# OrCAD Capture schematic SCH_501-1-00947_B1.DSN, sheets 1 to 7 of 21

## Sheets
1 P05_POWER DC-DC: size A2
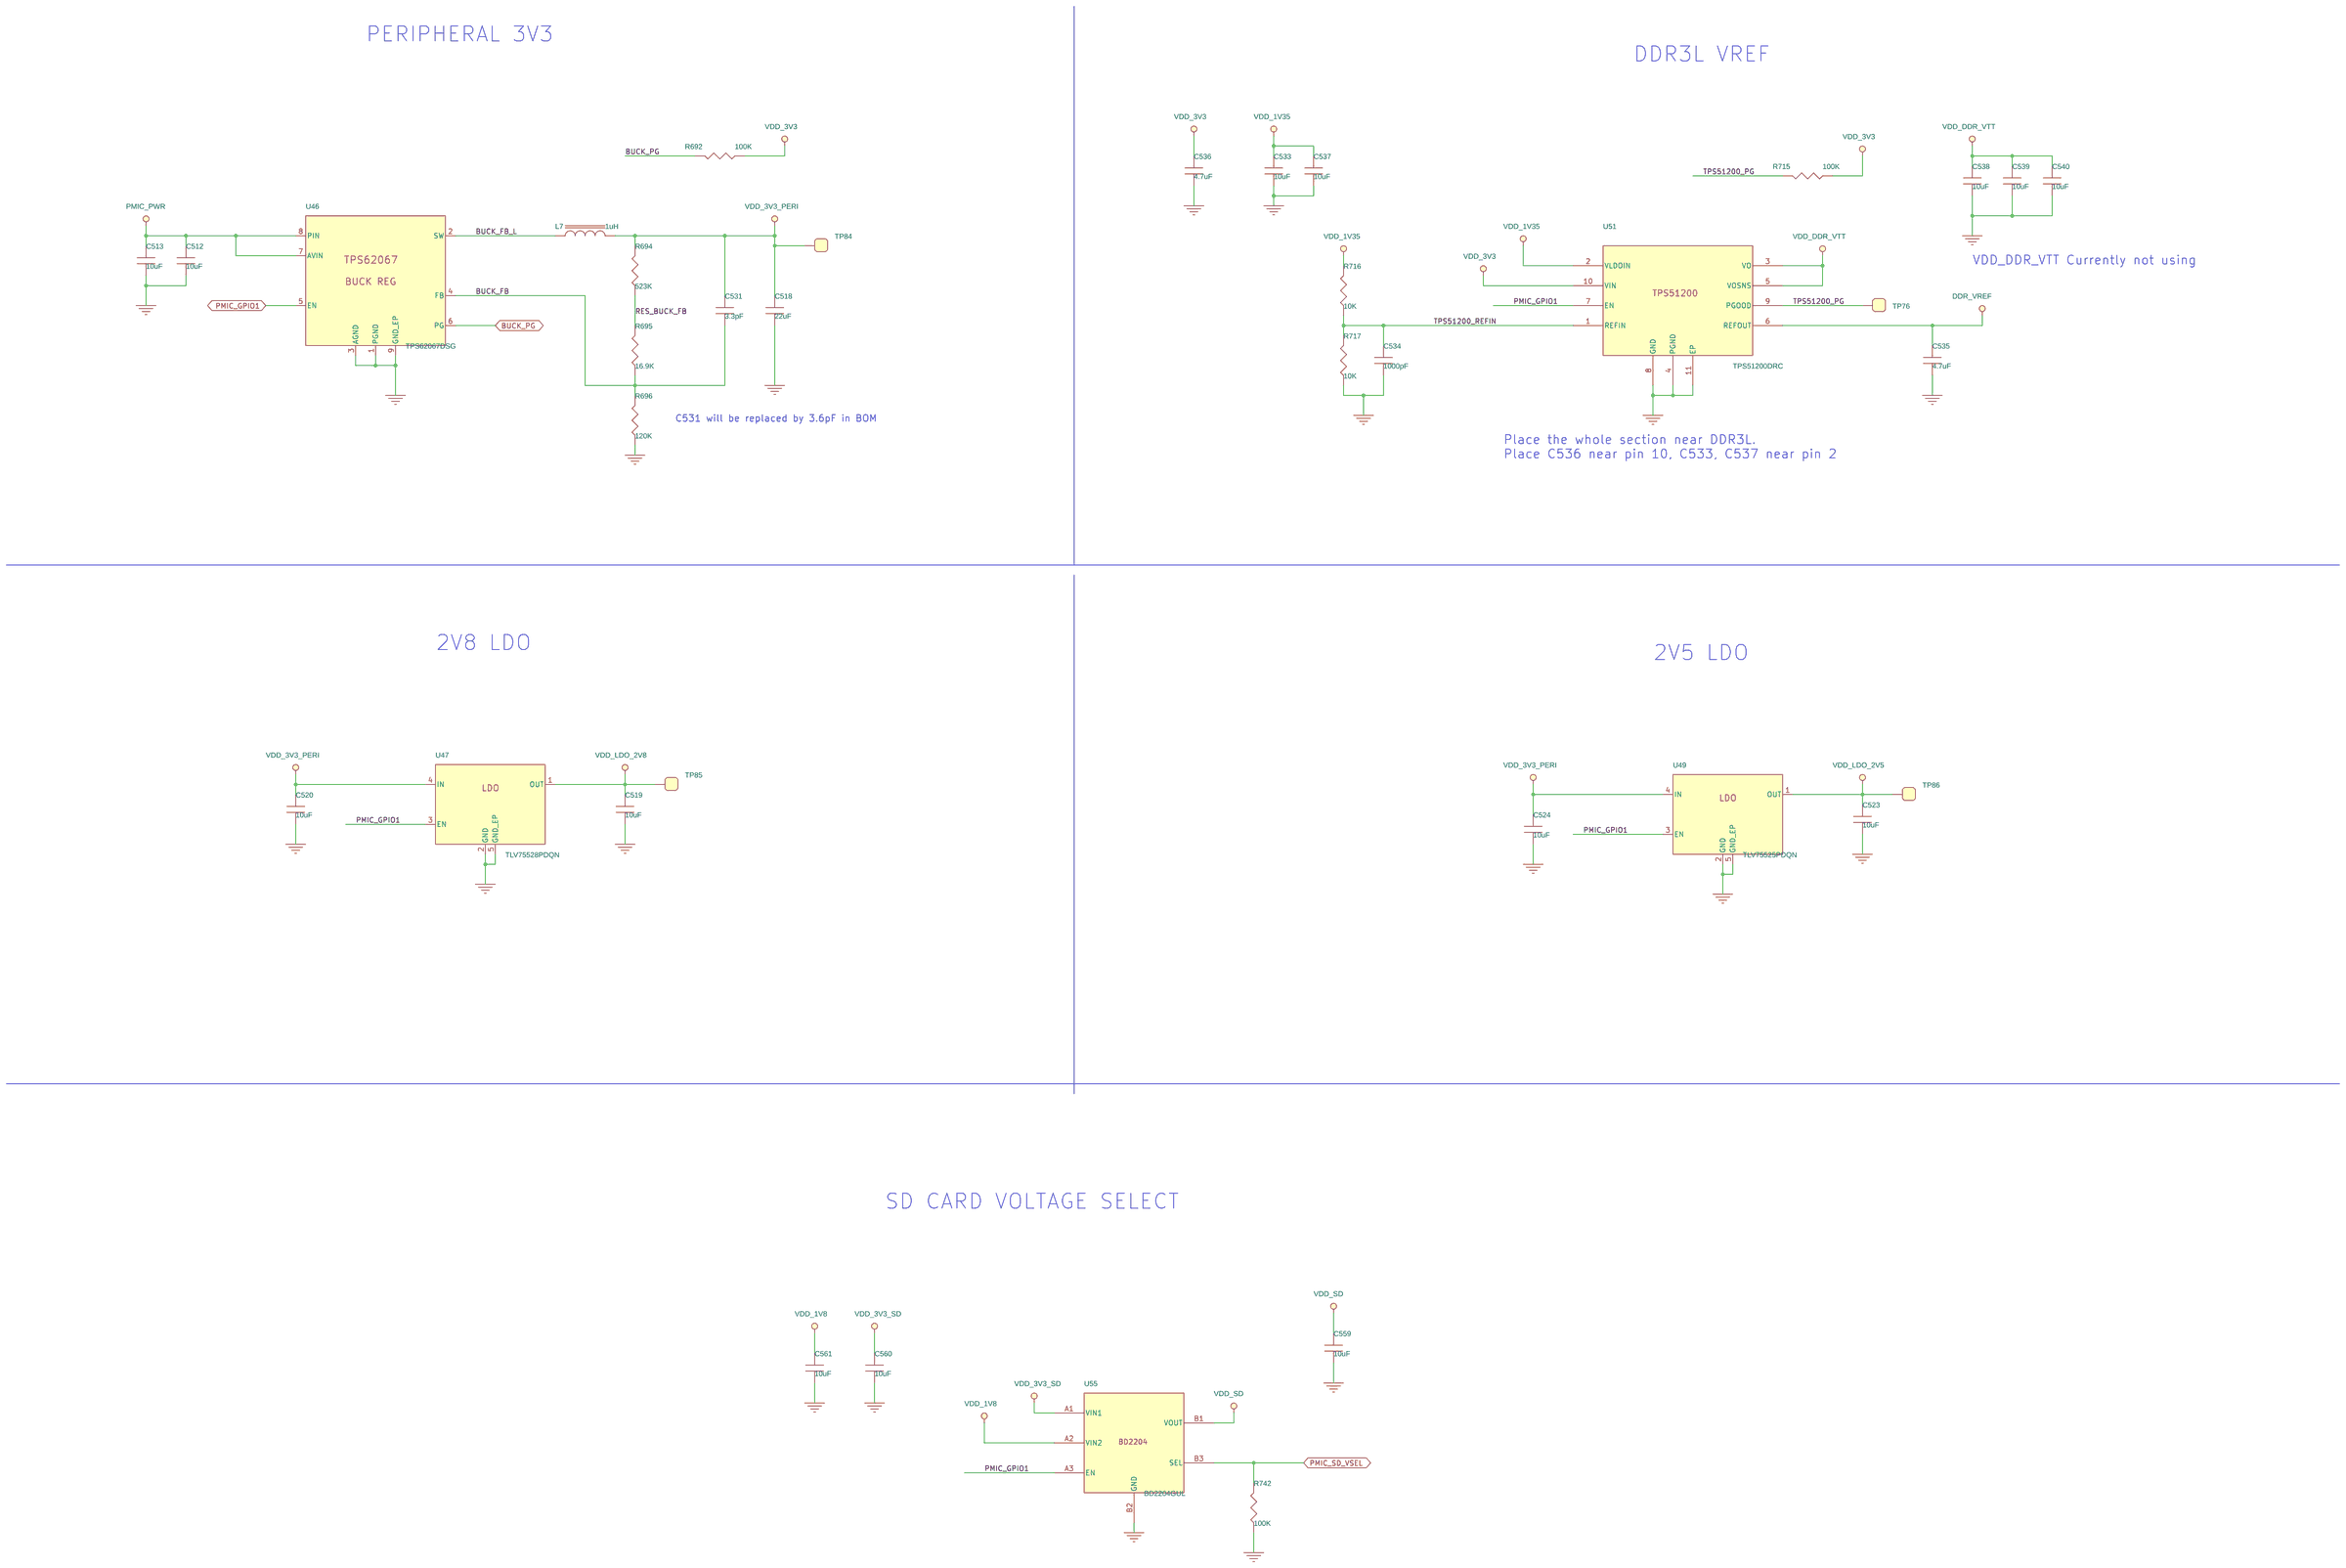
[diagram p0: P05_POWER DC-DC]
2 P01_COVER_PAGE
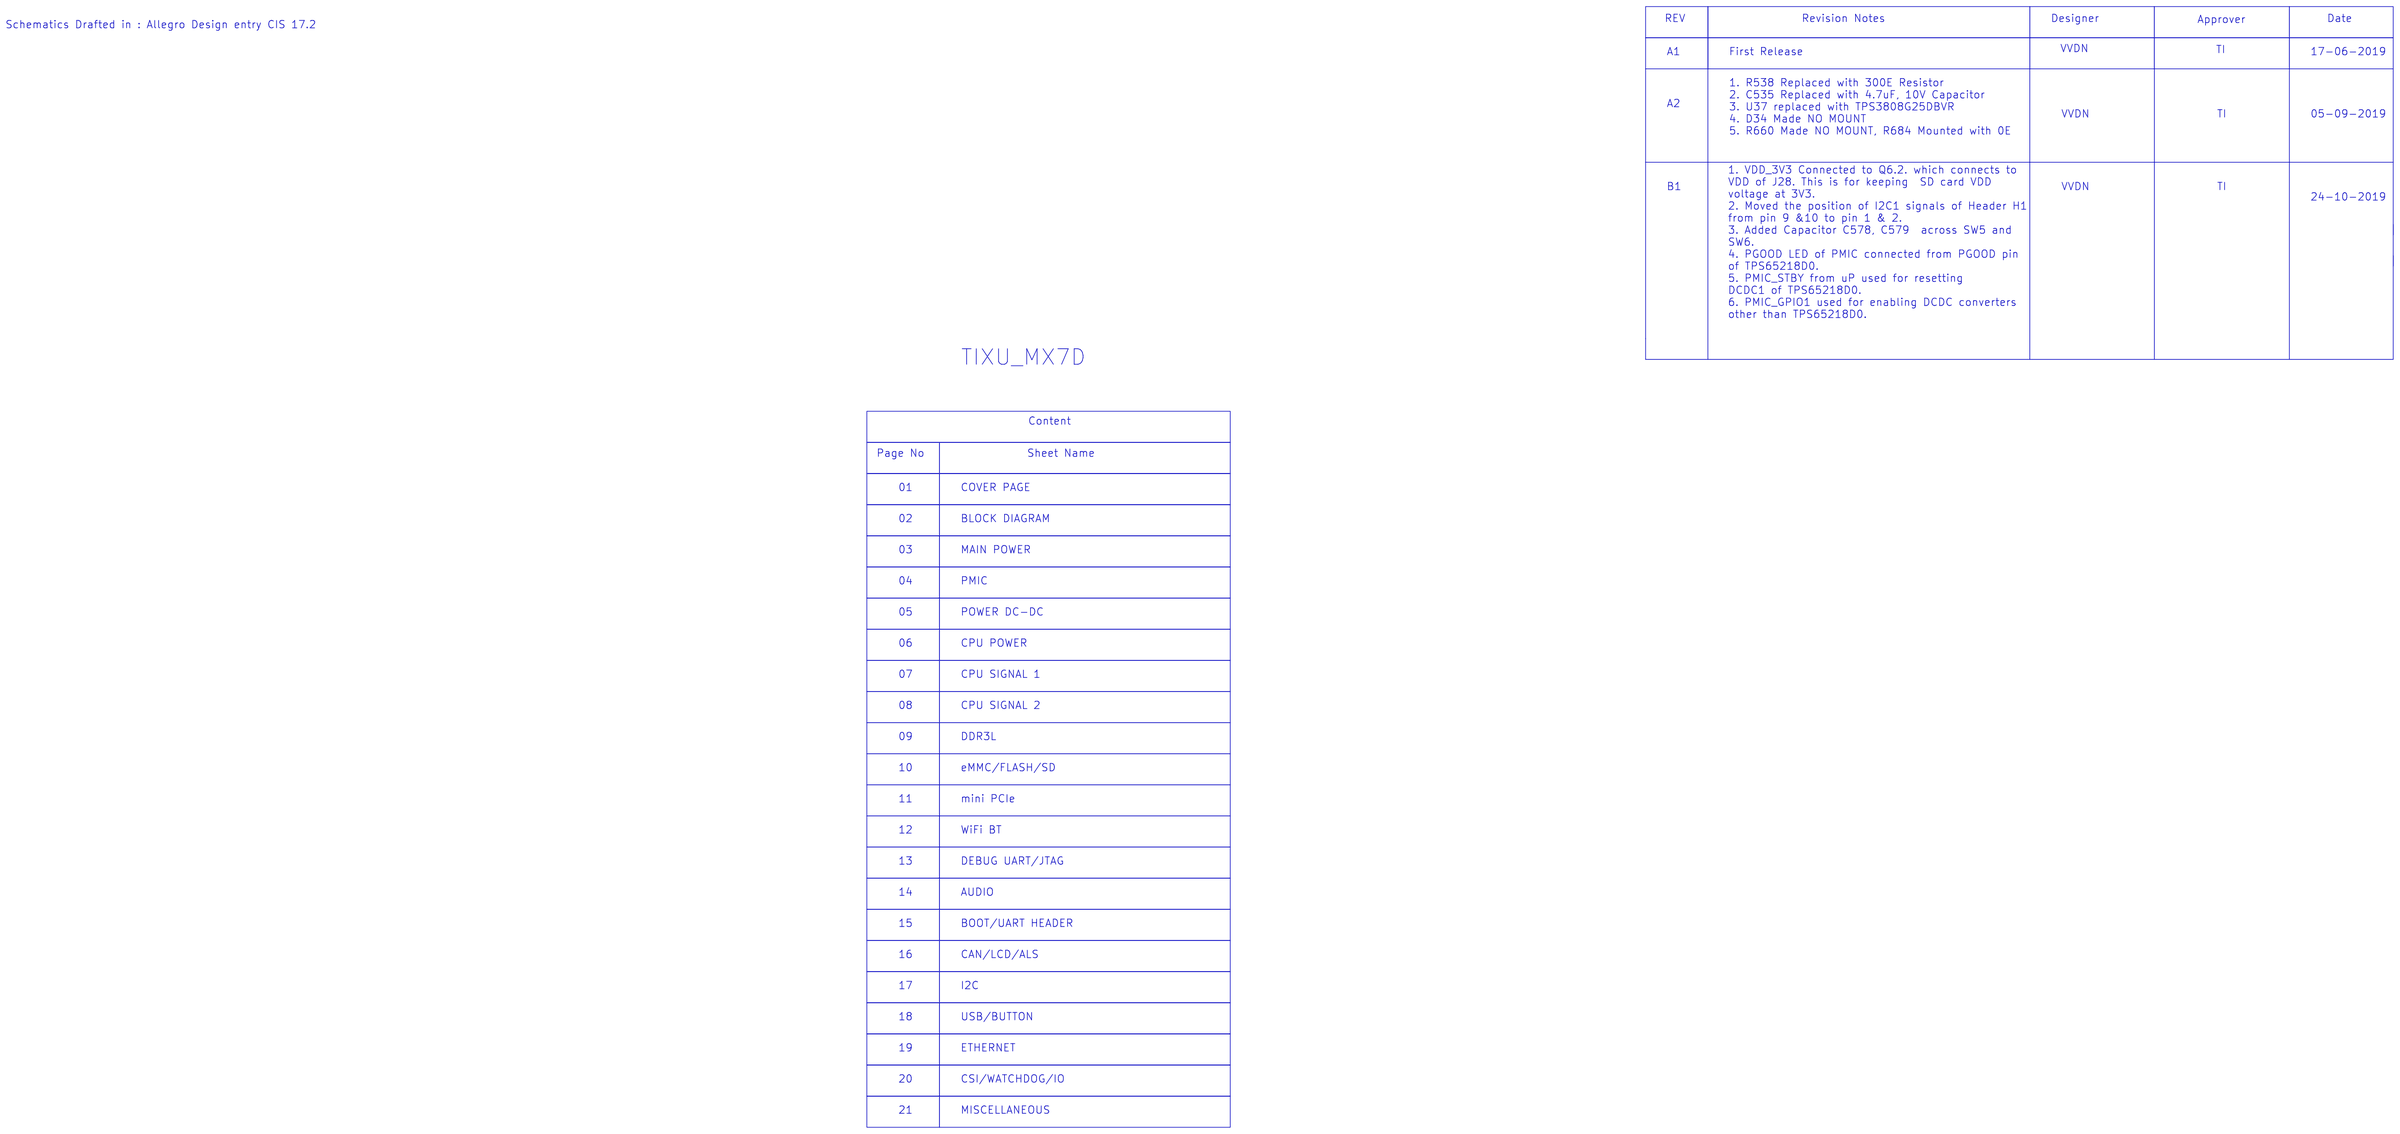
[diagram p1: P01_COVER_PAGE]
3 P02_BLOCK_DIAGRAM
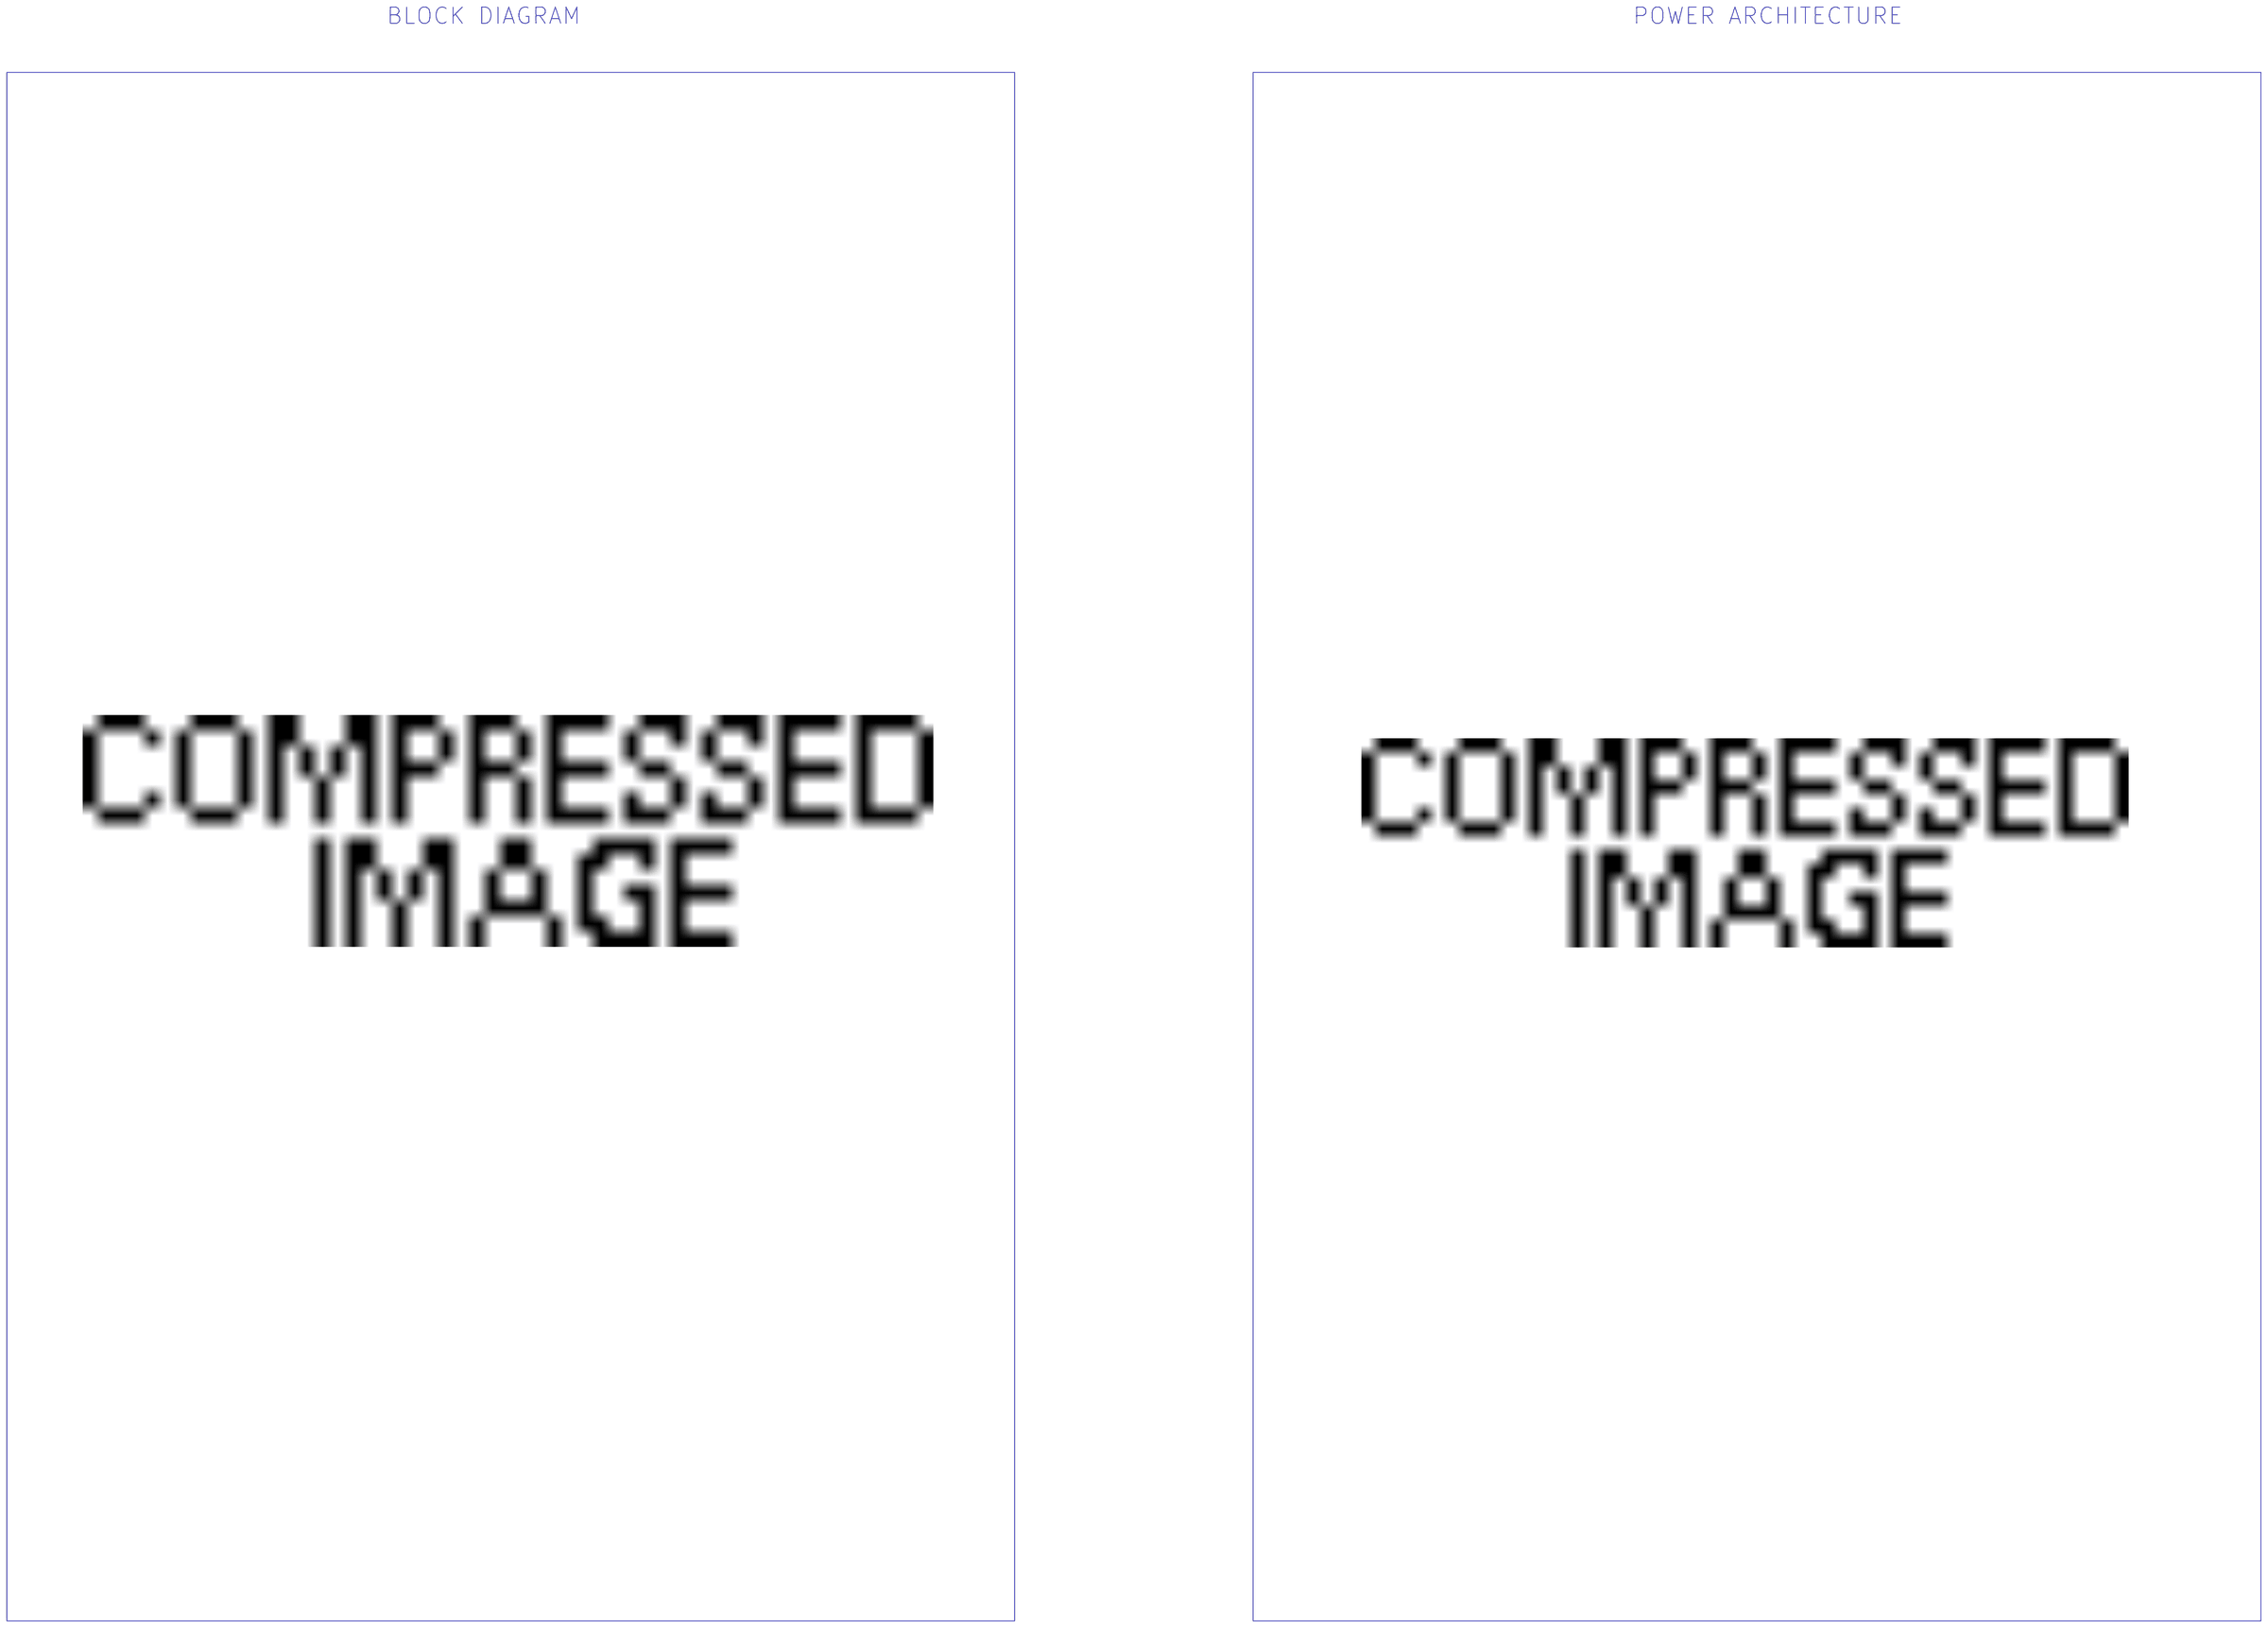
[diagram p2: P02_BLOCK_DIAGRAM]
4 P03_MAIN POWER: size A2
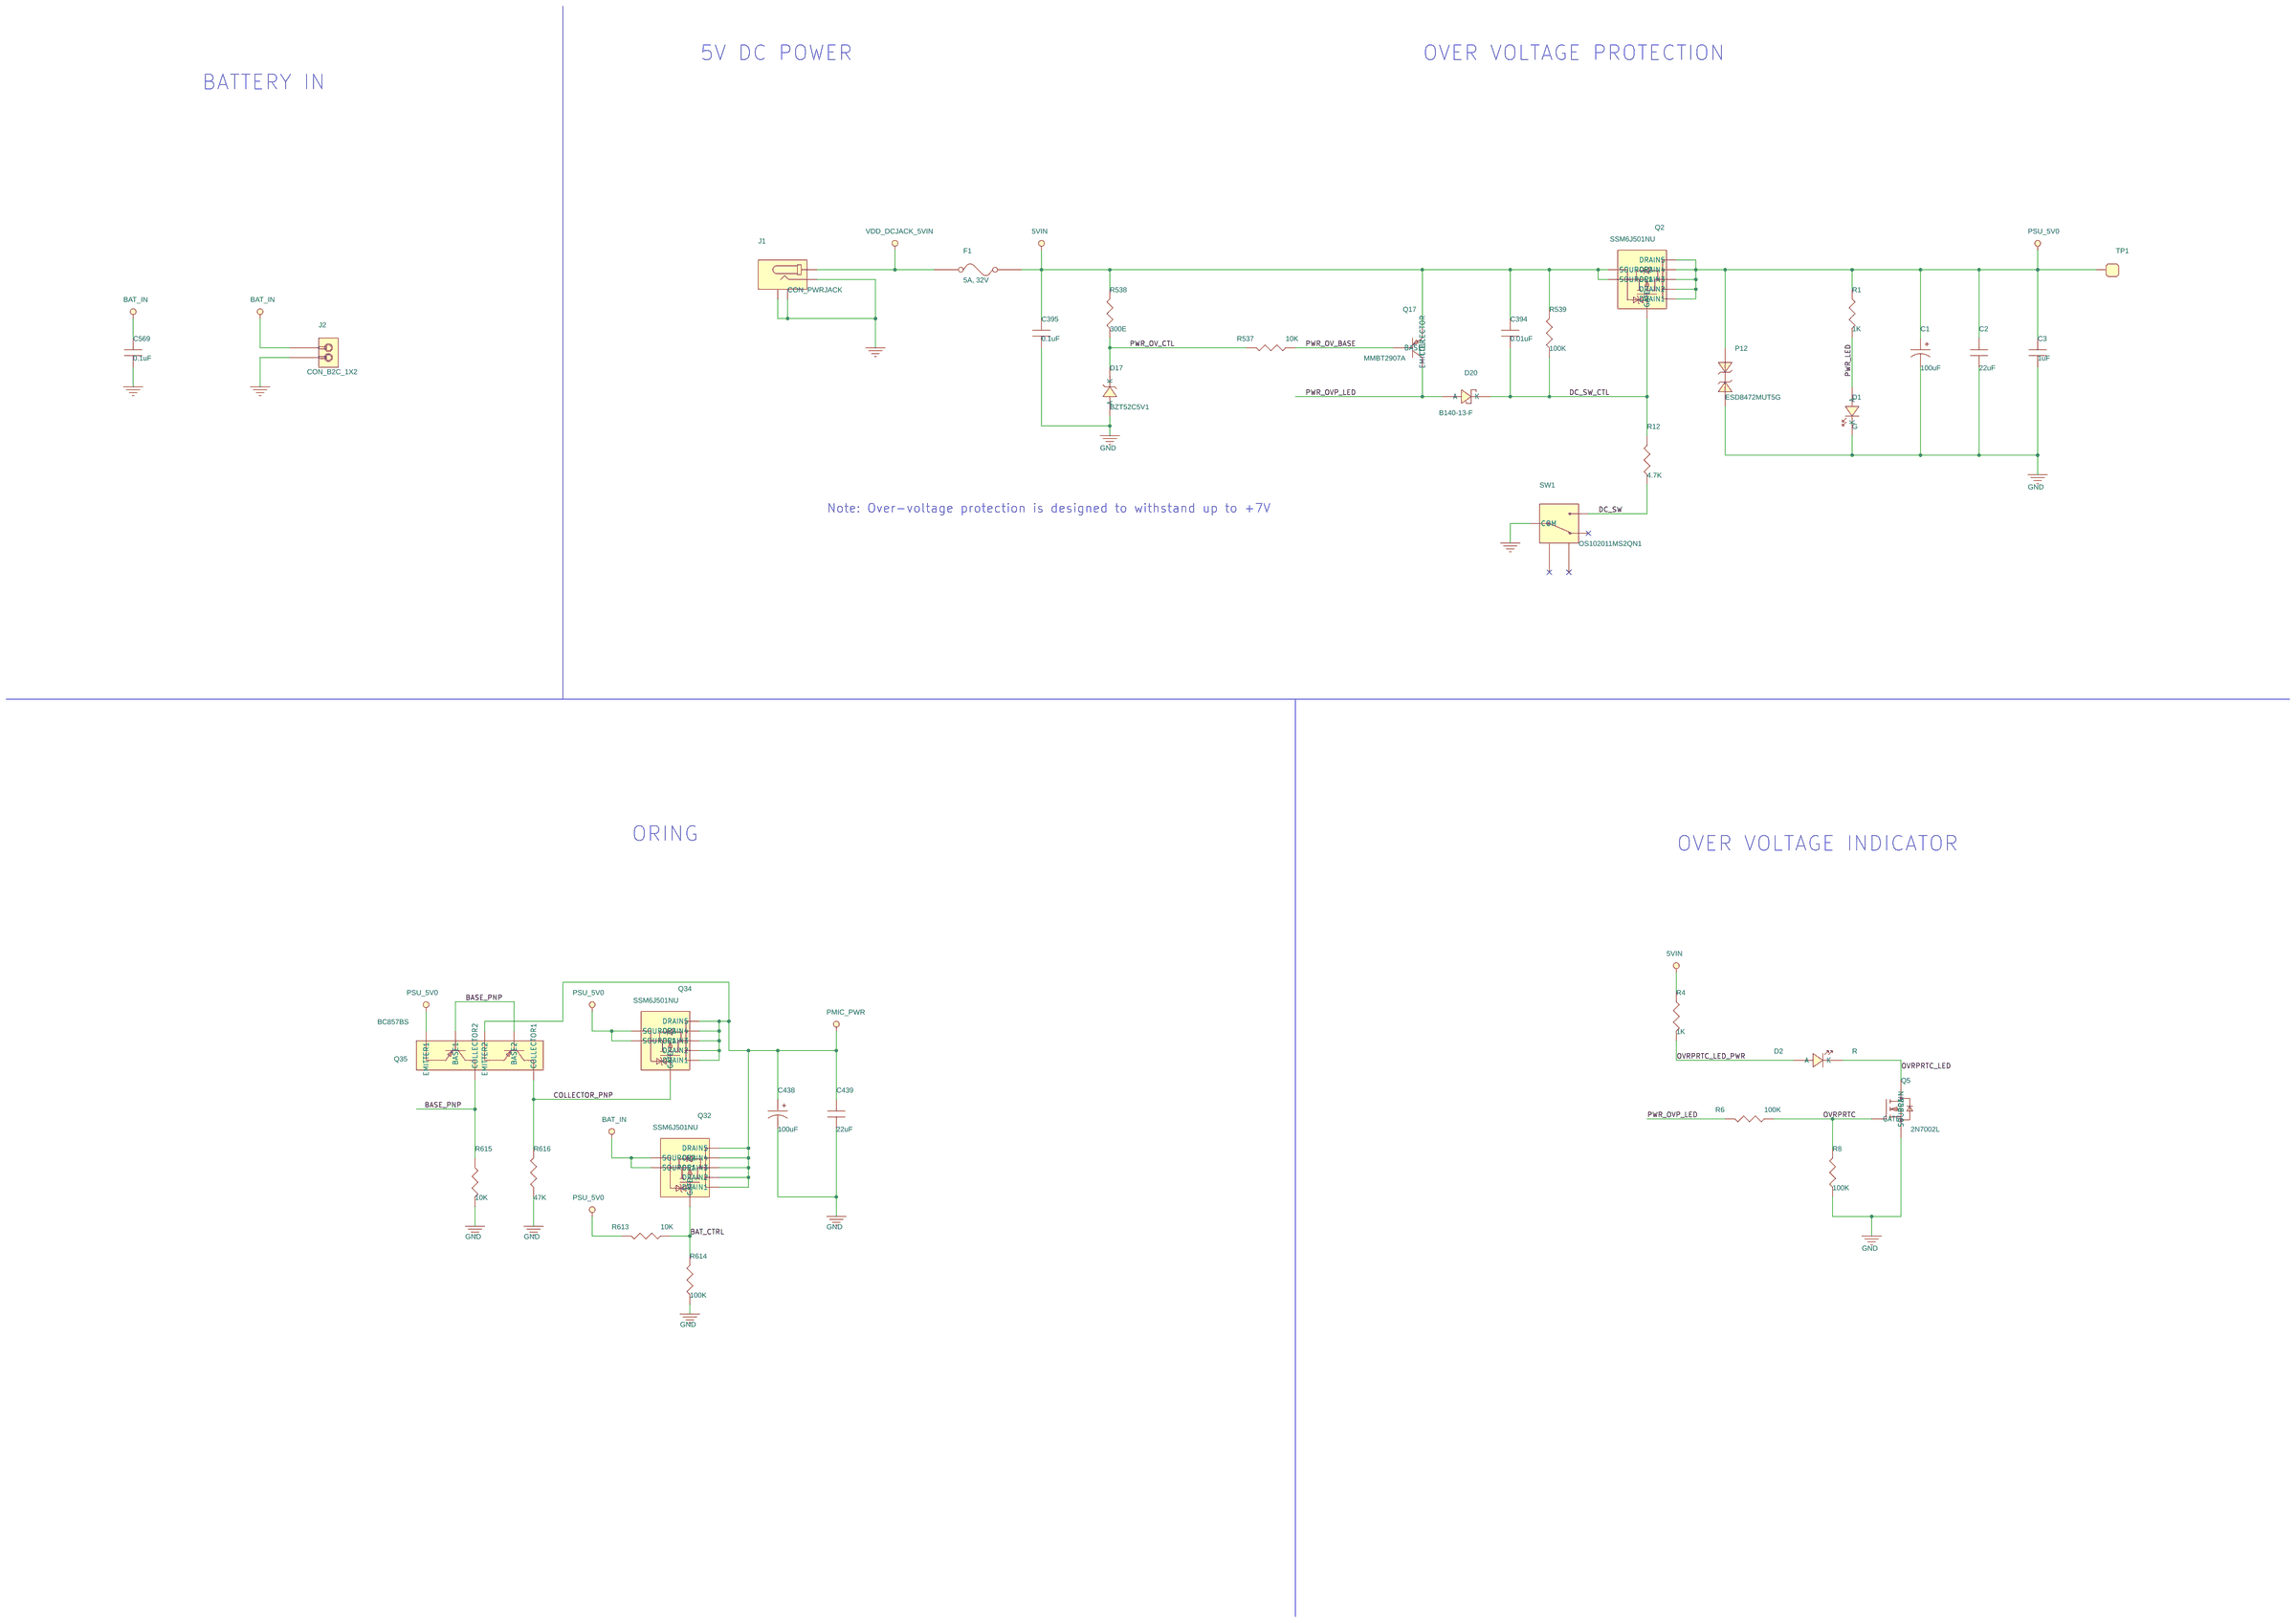
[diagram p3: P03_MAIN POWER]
5 P04_PMIC: size A2
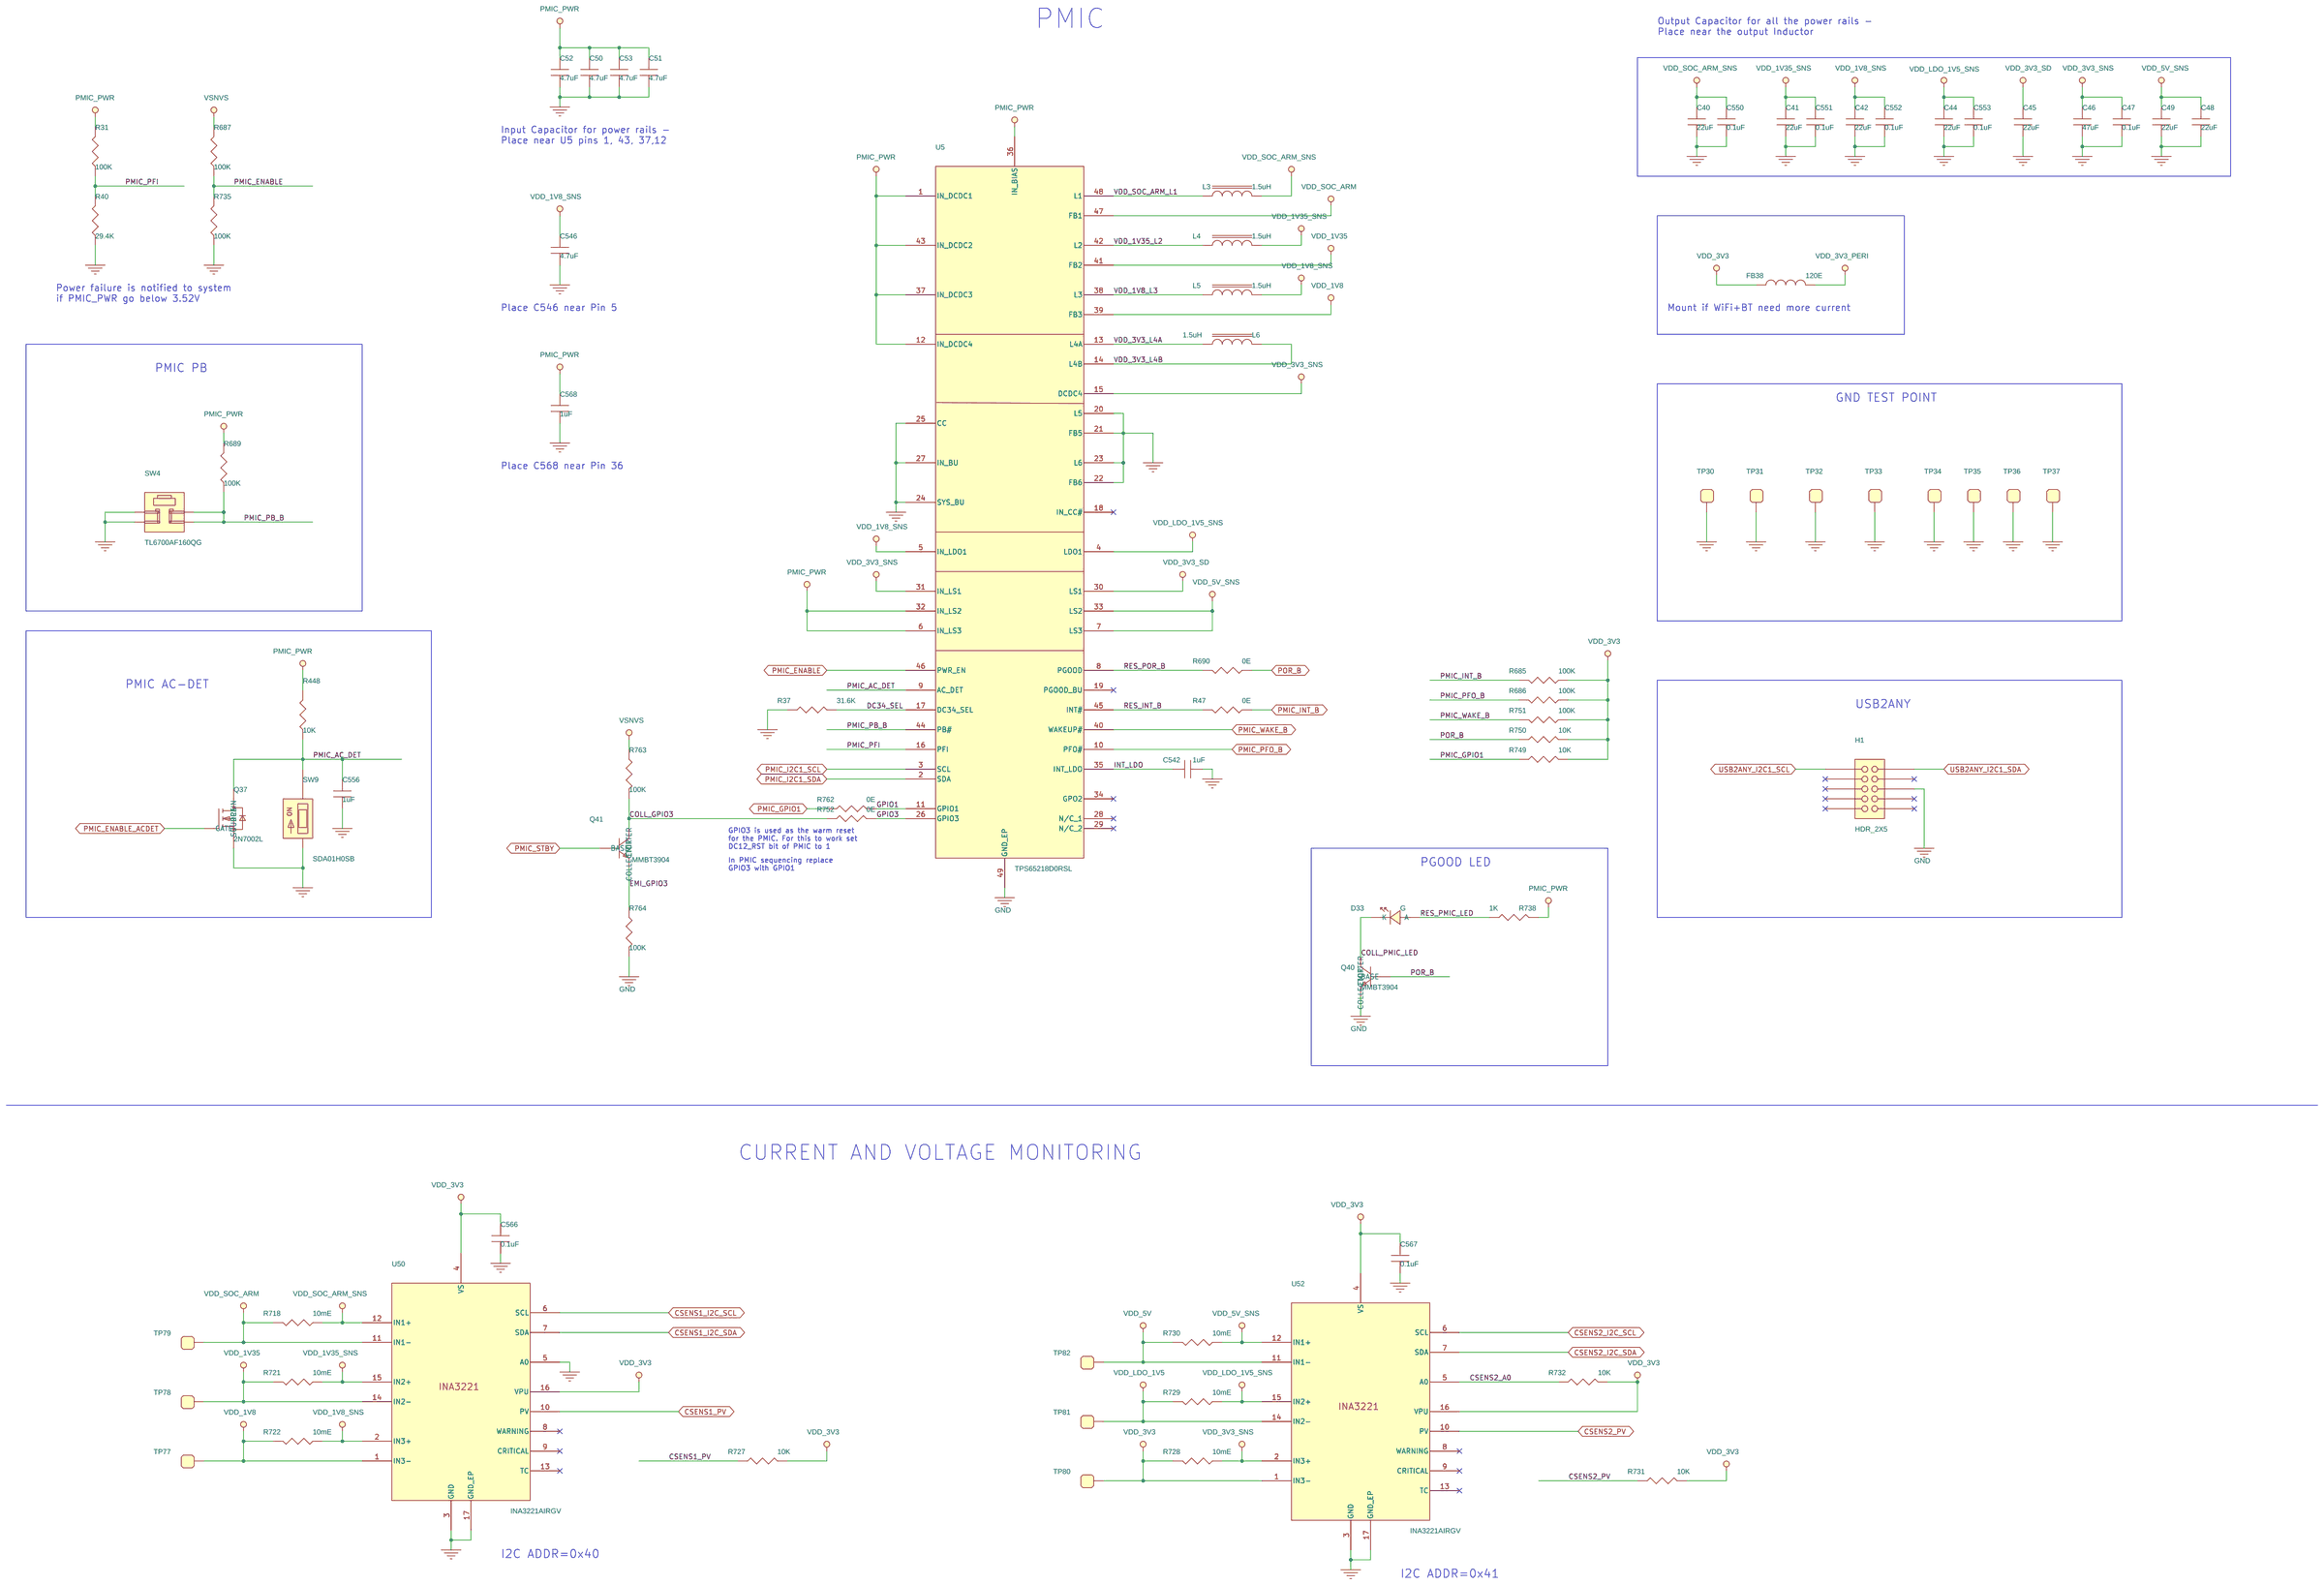
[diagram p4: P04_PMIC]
6 P06_CPU POWER: size A2
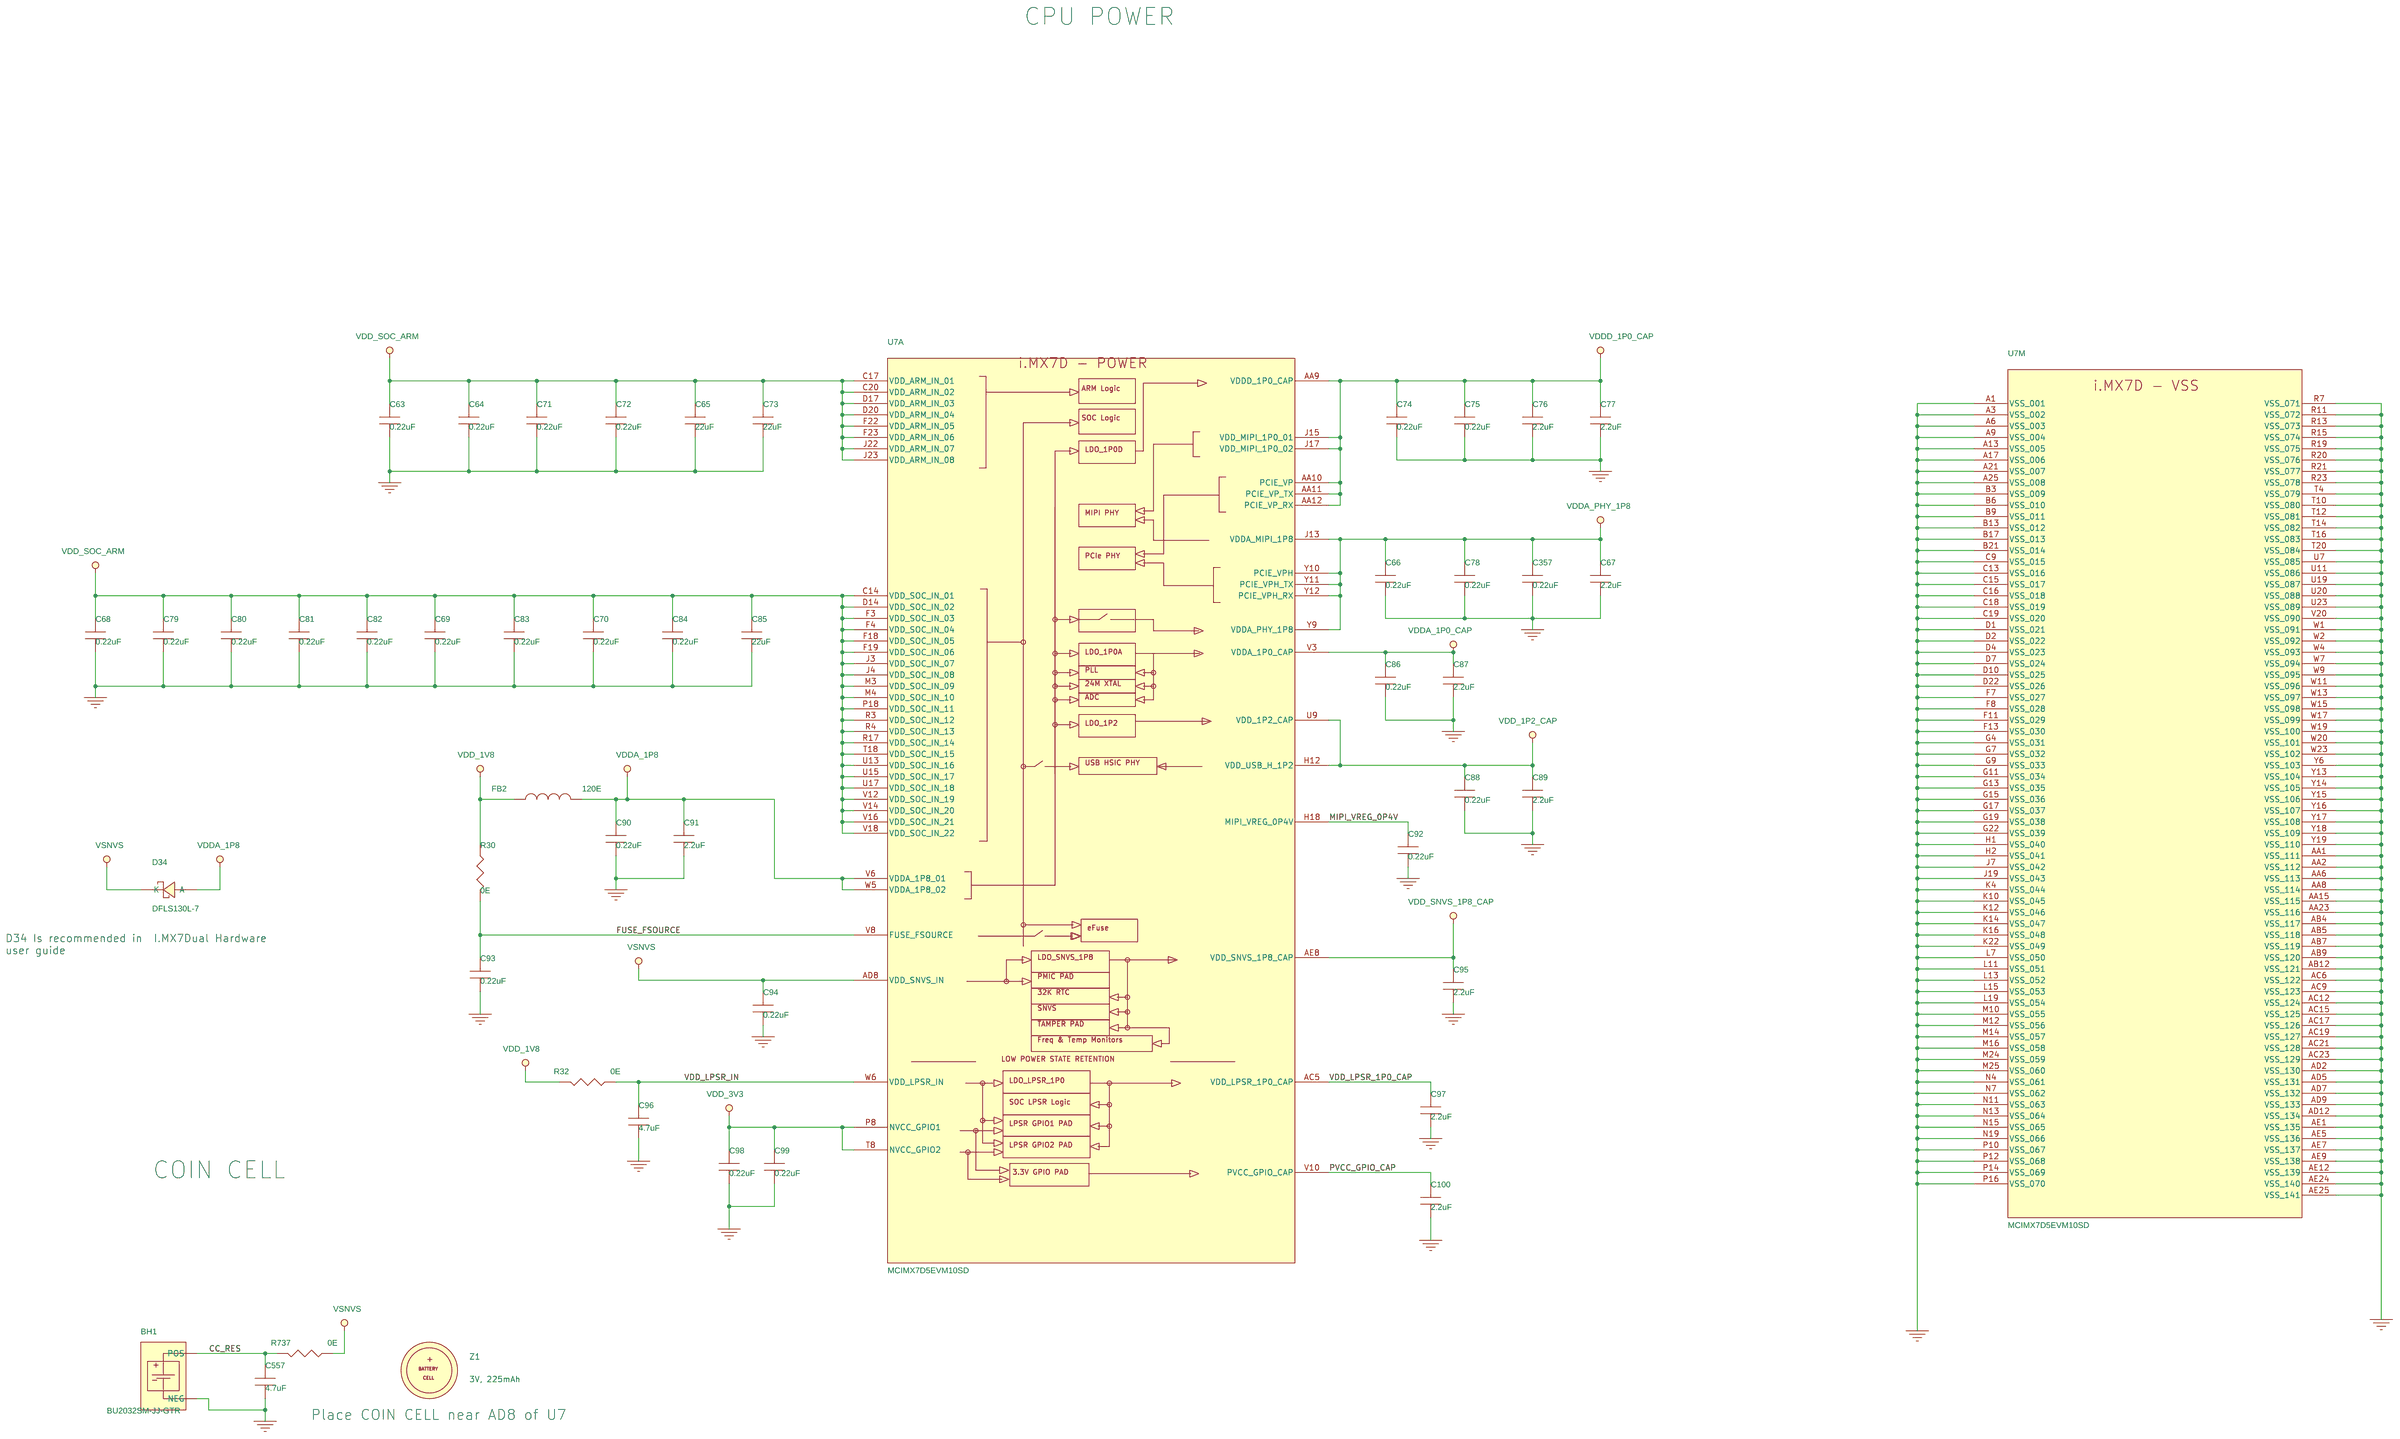
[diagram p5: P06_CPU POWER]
7 P07_CPU SIGNAL 1: size A2
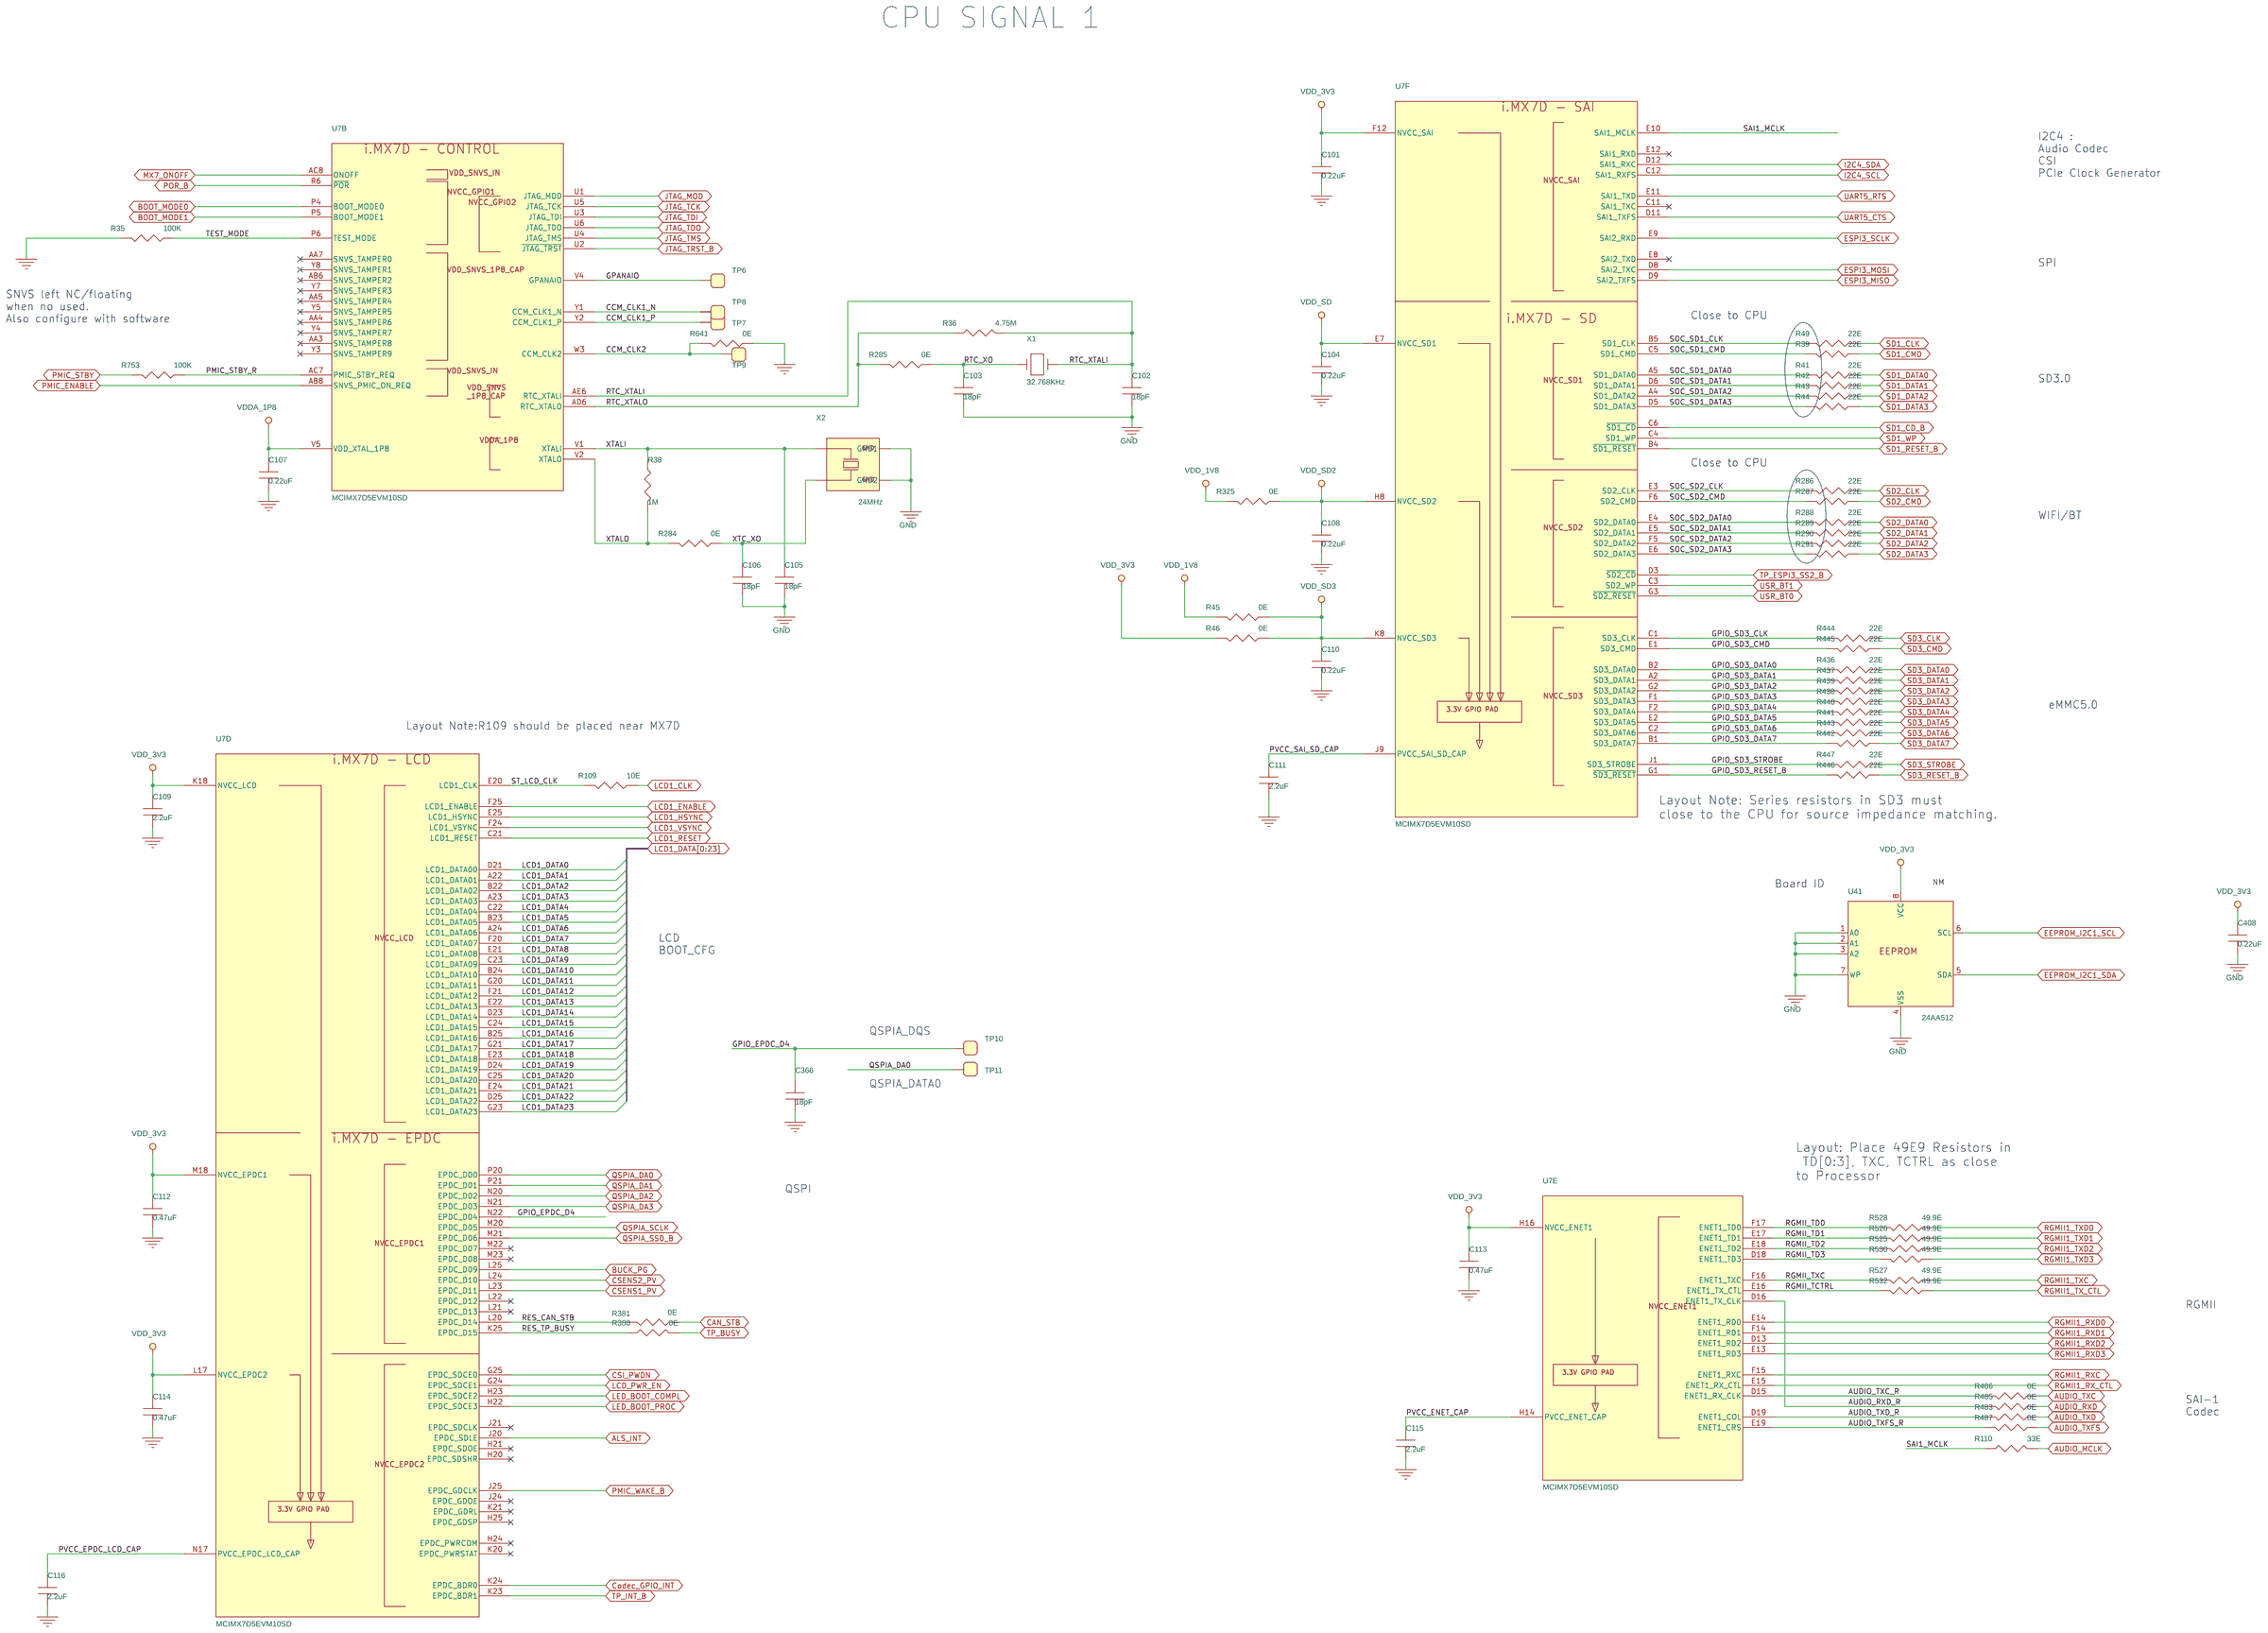
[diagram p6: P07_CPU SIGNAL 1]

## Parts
sheet P03_MAIN POWER
C1  100uF  [TCAP_CASEB]
C2  22uF  [C0603]
C3  1uF  [0402]
C394  0.01uF  [C0402]
C395  0.1uF  [C0402]
C438  100uF  [TCAP_CASEB]
C439  22uF  [C0603]
C569  0.1uF  [C0402]
D1  G  [LED2_1P5_1P6X0P8_A_A1]
D2  R  [LED-0603]
D17  BZT52C5V1  [DIO-SOD123_D_A1]
D20  B140-13-F  [DIO_SMA]
F1  5A, 32V  [FUSE_0603_0P64]
J1  CON_PWRJACK  [CON_PWR-JACK_2M_6_TH_RA_A_A1]
J2  CON_B2C_1X2  [CON_B2C_1X2M_2_TH_ST_A]
P12  ESD8472MUT5G  [DIO-0201]
Q2  SSM6J501NU  [UDFN-6L_0P65_2X2_EP]
Q5  2N7002L  [sot23_123]
Q17  MMBT2907A  [SOT23-3L_1P9_3P12X1P5]
Q32  SSM6J501NU  [UDFN-6L_0P65_2X2_EP]
Q34  SSM6J501NU  [UDFN-6L_0P65_2X2_EP]
Q35  BC857BS  [sot363_6]
R1  1K  [R0402]
R4  1K  [R0402]
R6  100K  [R0402]
R8  100K  [R0402]
R12  4.7K  [R0402]
R537  10K  [R0402]
R538  300E  [0402]
R539  100K  [R0402]
R613  10K  [R0402]
R614  100K  [R0402]
R615  10K  [R0402]
R616  47K  [R0402]
SW1  OS102011MS2QN1  [SW3_2_8P6X4P3_TH_ST]
TP1  SMD  [tp30]
sheet P04_PMIC
C40  22uF  [C0603]
C41  22uF  [C0603]
C42  22uF  [C0603]
C44  22uF  [C0603]
C45  22uF  [C0603]
C46  47uF  [0805_B_A1]
C47  0.1uF  [C0402]
C48  22uF  [C0603]
C49  22uF  [C0603]
C50  4.7uF  [C0603]
C51  4.7uF  [C0603]
C52  4.7uF  [C0603]
C53  4.7uF  [C0603]
C542  1uF  [C0603]
C546  4.7uF  [C0603]
C550  0.1uF  [C0402]
C551  0.1uF  [C0402]
C552  0.1uF  [C0402]
C553  0.1uF  [C0402]
C556  1uF  [C0603]
C566  0.1uF  [C0402]
C567  0.1uF  [C0402]
C568  1uF  [0402]
D33  G  [LED2_1P5_1P6X0P8_A_A1]
FB38  120E  [0402]
H1  HDR_2X5  [CON_BERG_2X5M_2P54_TH_RA]
L3  1.5uH  [IND_0806_B_A1]
L4  1.5uH  [IND_0806_B_A1]
L5  1.5uH  [IND_0806_B_A1]
L6  1.5uH  [IND_0806_B_A1]
Q37  2N7002L  [sot23_123]
Q40  MMBT3904  [sot23_123]
Q41  MMBT3904  [sot23_123]
R31  100K  [R0402]
R37  31.6K  [R0402]
R40  29.4K  [0402]
R47  0E  [R0402]
R448  10K  [R0402]
R685  100K  [R0402]
R686  100K  [R0402]
R687  100K  [R0402]
R689  100K  [R0402]
R690  0E  [R0402]
R718  10mE  [0603]
R721  10mE  [0603]
R722  10mE  [0603]
R727  10K  [R0402]
R728  10mE  [0603]
R729  10mE  [0603]
R730  10mE  [0603]
R731  10K  [R0402]
R732  10K  [R0402]
R735  100K  [R0402]
R738  1K  [R0402]
R749  10K  [R0402]
R750  10K  [R0402]
R751  100K  [R0402]
R752  0E  [R0402]
R762  0E  [R0402]
R763  100K  [R0402]
R764  100K  [R0402]
SW4  TL6700AF160QG  [SW4_4_6P9X6P2]
SW9  SDA01H0SB  [SW2_8P25_7P49X4P52]
TP30  SMD  [TP40_SMD]
TP31  SMD  [TP40_SMD]
TP32  SMD  [TP40_SMD]
TP33  SMD  [TP40_SMD]
TP34  SMD  [TP40_SMD]
TP35  SMD  [TP40_SMD]
TP36  SMD  [TP40_SMD]
TP37  SMD  [TP40_SMD]
TP77  SMD  [TP40_SMD]
TP78  SMD  [TP40_SMD]
TP79  SMD  [TP40_SMD]
TP80  SMD  [TP40_SMD]
TP81  SMD  [TP40_SMD]
TP82  SMD  [TP40_SMD]
U5  TPS65218D0RSL  [VQFN48_0P4_6X6_EP_A1]
U50  INA3221AIRGV  [QFN16_0P65_4X4_EP_I_A1]
U52  INA3221AIRGV  [QFN16_0P65_4X4_EP_I_A1]
sheet P05_POWER DC-DC
C512  10uF  [C0603]
C513  10uF  [C0603]
C518  22uF  [C0603]
C519  10uF  [C0603]
C520  10uF  [C0603]
C523  10uF  [C0603]
C524  10uF  [C0603]
C531  3.3pF  [0402]
C533  10uF  [C0603]
C534  1000pF  [C0402]
C535  4.7uF  [0402]
C536  4.7uF  [C0603]
C537  10uF  [C0603]
C538  10uF  [C0603]
C539  10uF  [C0603]
C540  10uF  [C0603]
C559  10uF  [C0603]
C560  10uF  [C0603]
C561  10uF  [C0603]
L7  1uH  [IND2_2P2_4X4]
R692  100K  [R0402]
R694  523K  [0402]
R695  16.9K  [0402]
R696  120K  [0402]
R715  100K  [R0402]
R716  10K  [0402]
R717  10K  [0402]
R742  100K  [R0402]
TP76  SMD  [tp30]
TP84  SMD  [TP40_SMD]
TP85  SMD  [TP40_SMD]
TP86  SMD  [TP40_SMD]
U46  TPS62067DSG  [SON8_0P5_2X2_EP]
U47  TLV75528PDQN  [X2SON4_0P65_1X1_EP_A_A1]
U49  TLV75525PDQN  [X2SON4_0P65_1X1_EP_A_A1]
U51  TPS51200DRC  [SON10_0P5_3P1X3P1]
U55  BD2204GUL  [VCSP50L1-6_0P5_1P5X1_A1]
sheet P06_CPU POWER
BH1  BU2032SM-JJ-GTR  [CON_BATTERY_2F_30P97_SM]
C63  0.22uF  [C0402]
C64  0.22uF  [C0402]
C65  22uF  [C0603]
C66  0.22uF  [C0402]
C67  2.2uF  [C0402]
C68  0.22uF  [C0402]
C69  0.22uF  [C0402]
C70  0.22uF  [C0402]
C71  0.22uF  [C0402]
C72  0.22uF  [C0402]
C73  22uF  [C0603]
C74  0.22uF  [C0402]
C75  0.22uF  [C0402]
C76  2.2uF  [C0402]
C77  2.2uF  [C0402]
C78  0.22uF  [C0402]
C79  0.22uF  [C0402]
C80  0.22uF  [C0402]
C81  0.22uF  [C0402]
C82  0.22uF  [C0402]
C83  0.22uF  [C0402]
C84  0.22uF  [C0402]
C85  22uF  [C0603]
C86  0.22uF  [C0402]
C87  2.2uF  [C0402]
C88  0.22uF  [C0402]
C89  2.2uF  [C0402]
C90  0.22uF  [C0402]
C91  2.2uF  [C0402]
C92  0.22uF  [C0402]
C93  0.22uF  [C0402]
C94  0.22uF  [C0402]
C95  2.2uF  [C0402]
C96  4.7uF  [C0603]
C97  2.2uF  [C0402]
C98  0.22uF  [C0402]
C99  0.22uF  [C0402]
C100  2.2uF  [C0402]
C357  0.22uF  [C0402]
C557  4.7uF  [C0603]
D34  DFLS130L-7  [DIO_POWERDI-123]
FB2  120E  [0402]
R30  0E  [R0402]
R32  0E  [R0402]
R737  0E  [R0402]
U7  MCIMX7D5EVM10SD  [bga541x]  (sections A,B,C,D,E,F,G,H,I,J,K,L,M)
Z1  3V, 225mAh  [BAT_3_22P9X5P8_TH_NCP]
sheet P07_CPU SIGNAL 1
C101  0.22uF  [C0402]
C102  18pF  [C0402]
C103  18pF  [C0402]
C104  0.22uF  [C0402]
C105  18pF  [C0402]
C106  18pF  [C0402]
C107  0.22uF  [C0402]
C108  0.22uF  [C0402]
C109  2.2uF  [C0402]
C110  0.22uF  [C0402]
C111  2.2uF  [C0402]
C112  0.47uF  [C0402]
C113  0.47uF  [C0402]
C114  0.47uF  [C0402]
C115  2.2uF  [C0402]
C116  2.2uF  [C0402]
C366  18pF  [C0402]
C408  0.22uF  [C0402]
R35  100K  [R0402]
R36  4.75M  [R0402]
R38  1M  [R0402]
R39  22E  [R0402]
R41  22E  [R0402]
R42  22E  [R0402]
R43  22E  [R0402]
R44  22E  [R0402]
R45  0E  [R0402]
R46  0E  [R0402]
R49  22E  [R0402]
R109  10E  [R0402]
R110  33E  [R0402]
R284  0E  [R0402]
R285  0E  [R0402]
R286  22E  [R0402]
R287  22E  [R0402]
R288  22E  [R0402]
R289  22E  [R0402]
R290  22E  [R0402]
R291  22E  [R0402]
R325  0E  [R0402]
R380  0E  [0402]
R381  0E  [0402]
R436  22E  [R0402]
R437  22E  [R0402]
R438  22E  [R0402]
R439  22E  [R0402]
R440  22E  [R0402]
R441  22E  [R0402]
R442  22E  [R0402]
R443  22E  [R0402]
R444  22E  [R0402]
R445  22E  [R0402]
R446  22E  [R0402]
R447  22E  [R0402]
R483  0E  [R0402]
R485  0E  [R0402]
R486  0E  [R0402]
R487  0E  [R0402]
R525  49.9E  [R0402]
R526  49.9E  [R0402]
R527  49.9E  [R0402]
R528  49.9E  [R0402]
R530  49.9E  [R0402]
R532  49.9E  [R0402]
R641  0E  [R0402]
R753  100K  [R0402]
TP6  SMD  [tp30]
TP7  SMD  [tp30]
TP8  SMD  [tp30]
TP9  SMD  [tp30]
TP10  SMD  [tp30]
TP11  SMD  [tp30]
U41  24AA512  [so8_1p27_4x5]
X1  32.768KHz  [XTAL2_2P5_3P2X1P5]
X2  24MHz  [XTAL4_1P85_3P2X2P5]

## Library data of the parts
C1 C438 = CAP_POL: Cap, Tant, 100uF, 10V, 20%, SizeB; EN: 102-2-00272; KEY Number: 102-2-00272@1; Mfg: AVX CORPORATION; Mfg Part No: TAJB107M010RNJ
C2 C40-C42 C44 C45 C48 C49 C65 C73 C85 C439 C518 = CAP_NP: Cap, Cer-X5R, 22uF, 10V, 20%, 0603; EN: 102-1-01791; KEY Number: 102-1-01791@5; Mfg: MURATA MANUFACTURING CO,LTD; Mfg Part No: GRM188R61A226ME15*; Temperature: -55°C to +85°C
C3 C568 = CAP_NP: Cap, Cer-X7R, 1uF, 16V, 10%, 0402; EN: 102-1-02367; KEY Number: 102-1-02367@1; Mfg: CAPAX TECHNOLOGIES INC.; Mfg Part No: 0402X105K160SNW; Temperature: -55°C to +125°C
C394 = CAP_NP: Cap, Cer-X7R, 0.01uF, 25V, 10%, 0402; EN: 102-1-00027; FPLIST: 0402,0402_CIR; KEY Number: 102-1-00027@3; Mfg: WALSIN TECHNOLOGY CORP.; Mfg Part No: 0402B103K250; Temperature: -55°C to +125°C
C395 = CAP_NP: Cap, Cer-X5R, 0.1uF, 25V, 10%, 0402; EN: 102-1-01693; FPLIST: 0402,0402_CIR_A1; KEY Number: 102-1-01693@1; Mfg: AVX CORPORATION; Mfg Part No: 04023D104KAT2A; Temperature: -55°C to +85°C
C47 C550-C553 C566 C567 C569 = CAP_NP: Cap, Cer-X7R, 0.1uF, 16V, 10%, 0402; EN: 102-1-01629; KEY Number: 102-1-01629@4; Mfg: MURATA MANUFACTURING CO,LTD; Mfg Part No: GRM155R71C104KA88*; Temperature: -55°C to +125°C
D1 D33 = DIODE_LED: LED, Single, Green, SMD; EN: 106-4-00248; KEY Number: 106-4-00248@1; Mfg: LITE-ON; Mfg Part No: LTST-C193KGKT-5A; Temperature: -55°C to +85°C
D2 = DIODE_LED: LED, Single, Red, 0603; EN: 106-4-00009; KEY Number: 106-4-00009@1; Mfg: LUMEX; Mfg Part No: SML-LX0603IW-TR; Temperature: -25°C to +85°C
D17 = DIODE_ZEN: Diode, Zener, 5.1V, 5mA, 0.5W, SOD-123; EN: 106-3-00071; KEY Number: 106-3-00071@1; Mfg: VISHAY; Mfg Part No: BZT52C5V1-HE3-*; Temperature: -55°C to +150°C
D20 = DIODE_SCH: Diode, Schottky, 1A, 40V, SMA; EN: 106-2-00036; KEY Number: 106-2-00036@1; Mfg: DIODES INCORPORATED
F1 = FUSE: Fuse, Blow, Fast, 5A, 32V DC, SMD; EN: 305-1-00145; KEY Number: 305-1-00145@1; Mfg: PANASONIC; Mfg Part No: ERBRE5R00; Temperature: -40°C to +125°C
J1 = CONN_PWRJACK_4P_A_A1: Conn, DC PWR Jack, 1x1, 8A, 2.5mm ID, 6.5mm OD,  RA, TH; EN: 201-2-01385; KEY Number: 201-2-01385@1; Mfg: CUI INC; Mfg Part No: PJ-063BH; Temperature: -25°C to +85°C
J2 = CONN_B2C_1X2_2P: Conn, B2C, Male, 1x2, 2mm, 2A, Semi-Shrouded, Lock, ST, TH; EN: 201-1-00196; KEY Number: 201-1-00196@1; Mfg: JST; Mfg Part No: B2B-PH-K-S(LF)(SN)
P12 = PROT_ZENX2_NET_2P_A: TVS-Zener Diode, Bi, 7V, X3DFN2; EN: 305-1-00135; KEY Number: 305-1-00135@1; Mfg: ON SEMICONDUCTOR; Temperature: -55°C to +150°C
Q2 Q32 Q34 = TRANS_PMOSX1_8P: Transistor, P-MOSFET, 20V, 10A, Vgs=8V, 1W, UDFN-6B; EN: 107-2-00034; KEY Number: 107-2-00034@1; Mfg: TOSHIBA CORPORATION
Q5 Q37 = TRANS_NMOS-ENX1_3P: Transistor, N-MOSFET, 60V, 0.115A, Vgs=20V, 0.225W, SOT-23; EN: 107-2-00143; KEY Number: 107-2-00143@1; Mfg: ON SEMICONDUCTOR; Mfg Part No: 2N7002L**G; Temperature: -55°C to +150°C
Q17 = TRANS_PNP: Transistor, BJT, PNP, 60V, 0.8A, 0.35W, SOT23-3; EN: 107-1-00031; KEY Number: 107-1-00031@1; Mfg: FAIRCHILD SEMICONDUCTOR; Temperature: -55°C to +155°C
Q35 = TRANS_PNPX2_6P_A1: Transistor, BJT, Dual PNP, 45V, 0.1A, 0.2W, SOT363-6; EN: 107-1-00096; KEY Number: 107-1-00096@1; Mfg: NEXPERIA; Mfg Part No: BC857BS,115; Temperature: -65°C to +150°C
R1 R4 R738 = RES: Res, Chip, 1K, 1/16W, 5%, 0402; EN: 101-1-02769; KEY Number: 101-1-02769@4; Mfg: WALSIN TECHNOLOGY CORP.; Mfg Part No: WR04X102JTL; Temperature: -55°C to +155°C
R6 R8 R31 R35 R539 R614 R685-R687 R689 R692 R715 R735 R742 R751 R753 R763 R764 = RES: Res, Chip, 100K, 1/16W, 1%, 0402; EN: 101-1-00485; KEY Number: 101-1-00485@3; Mfg: WALSIN TECHNOLOGY CORP.; Mfg Part No: WR04X1003FTL; Temperature: -55°C to +155°C
R12 = RES: Res, Chip, 4.7K, 1/16W, 1%, 0402; EN: 101-1-03446; KEY Number: 101-1-03446@2; Mfg: WALSIN TECHNOLOGY CORP.; Mfg Part No: WR04X4701FTL; Temperature: -55°C to +155°C
R448 R537 R613 R615 R727 R731 R732 R749 R750 = RES: Res, Chip, 10K, 1/16W, 5%, 0402; EN: 101-1-02793; KEY Number: 101-1-02793@2; Mfg: VISHAY; Mfg Part No: CRCW040210K0JNED; Temperature: -55°C to +155°C
R538 = RES: Res, Chip, 300E, 1/16W, 5%, 0402; EN: 101-1-02756; KEY Number: 101-1-02756@2; Mfg: VISHAY; Mfg Part No: CRCW0402300RJNED; Temperature: -55°C to +155°C
R616 = RES: Res, Chip, 47K, 1/16W, 1%, 0402; EN: 101-1-03402; KEY Number: 101-1-03402@2; Mfg: WALSIN TECHNOLOGY CORP.; Mfg Part No: WR04X4702FTL; Temperature: -55°C to +155°C
SW1 = SWITCH_SPDT_5P: Switch, Slide, SPDT, 12V, Vertical, TH; EN: 205-1-00079; KEY Number: 205-1-00079@1; Mfg: C&K COMPONENTS; Temperature: -30°C to +70°C
TP1 TP6-TP11 TP30-TP37 TP76-TP82 TP84-TP86 = TEST_POINT_SMD: Testpoint, Pad=1mm, SM=1.3mm, SMD; EN: 666-1-00008; KEY Number: 666-1-00008@1; Mfg: NA; Mfg Part No: 666-1-00008
C46 = CAP_NP: Cap, Cer-X5R, 47uF, 10V, 20%, 0805; EN: 102-1-02136; KEY Number: 102-1-02136@1; Mfg: MURATA MANUFACTURING CO,LTD; Mfg Part No: GRM21BR61A476ME15L; Temperature: -55°C to +85°C
C50-C53 C536 C546 = CAP_NP: Cap, Cer-X5R, 4.7uF, 16V, 10%, 0603; EN: 102-1-00091; FPLIST: 0603,0603_HD; KEY Number: 102-1-00091@4; Mfg: MURATA MANUFACTURING CO,LTD; Mfg Part No: GRM188R61C475KAAJ*; Temperature: -55°C to +85°C
C542 C556 = CAP_NP: Cap, Cer-X7R, 1uF, 10V, 10%, 0603; EN: 102-1-00097; FPLIST: 0603,0603_HD; KEY Number: 102-1-00097@1; Mfg: AVX CORPORATION; Mfg Part No: 0603ZC105KAT2A; Temperature: -55°C to +125°C
FB2 FB38 = FER_BEAD: F-Bead, 120E, 1.3A, SMD0402; EN: 104-1-00007; KEY Number: 104-1-00007@1; Mfg: MURATA MANUFACTURING CO,LTD; Mfg Part No: BLM15PD121SN1B; Temperature: -55°C to +125°C
H1 = HDR_2X5_10P: Conn, Berg strip, 2x5, 2.54mm, 3A, RA, TH; EN: 201-2-00352; KEY Number: 201-2-00352@1; Mfg: FCI; Mfg Part No: 68021-210HLF; Temperature: -65°C to +125°C
L3-L6 = IND_CORE_A: Ind, Power, 1.5uH, 20%, 1.8A, 110mE, Shielded, SMD0806; EN: 103-1-00424; KEY Number: 103-1-00424@2; Mfg: MURATA MANUFACTURING CO,LTD; Mfg Part No: DFE201610P-1R5M; Temperature: -40°C to +125°C
Q40 Q41 = TRANS_NPN: Transistor, BJT, NPN, 40V, 0.2A, SOT23-3; EN: 107-1-00001; KEY Number: 107-1-00001@1; Mfg: FAIRCHILD SEMICONDUCTOR; Temperature: -55°C to +150°C
R37 = RES: Res, Chip, 31.6K, 1/16W, 1%, 0402; EN: 101-1-00437; KEY Number: 101-1-00437@2; Mfg: VISHAY; Mfg Part No: CRCW040231K6FK**; Temperature: -55°C to +155°C
R40 = RES: Res, Chip, 29.4K, 1/16W, 1%, 0402; EN: 101-1-00434; KEY Number: 101-1-00434@2; Mfg: VISHAY; Mfg Part No: CRCW040229K4FK; Temperature: -55°C to +155°C
R30 R32 R45-R47 R284 R285 R325 R380 R381 R483 R485-R487 R641 R690 R737 R752 R762 = RES: Res, Chip, 0E, 1/16W, 1.5A, AEC-Q200, 0402; EN: 101-1-00001; KEY Number: 101-1-00001@2; Mfg: VISHAY; Mfg Part No: CRCW04020000Z0ED; Temperature: -55°C to +155°C
R718 R721 R722 R728-R730 = RES: Res, I-Sense, 10mE, 1/4W, 1%, 0603; EN: 101-3-00046; KEY Number: 101-3-00046@2; Mfg: WALSIN TECHNOLOGY CORP.; Mfg Part No: WW06CR010FTL; Temperature: -55°C to +125°C
SW4 = SWITCH_PUSH_4P: Switch, Tactile, SPST-NO, 12V, 50mA, Vertical, SMD; EN: 205-1-00113; KEY Number: 205-1-00113@1; Mfg: E-SWITCH; Temperature: -20°C to +70°C
SW9 = SWITCH_DIPX1_2P_B: Switch, DIP, 1 Position, 25mA, Vertical, SMD; EN: 205-1-00059; KEY Number: 205-1-00059@1; Mfg: C&K COMPONENTS; Temperature: -40°C to +85°C
U5 = TMP_0: IC, TPS65218D0, PMIC, 7 Outputs, 6-DC/DCs&1-LDOs, (Programmed version), VQFN-48; EN: 301-4-01045; KEY Number: 301-4-01045@1; Mfg: TEXAS INSTRUMENTS; Mfg Part No: TPS65218D0RSLT; Temperature: -40°C to +105°C
U50 U52 = IC_INA3221_VQFN-16P_EP_A1: IC, INA3221, 3-Channel, High side Current/Voltage Monitor with I2C, VQFN-16; EN: 301-0-02543; KEY Number: 301-0-02543@1; Mfg: TEXAS INSTRUMENTS; Mfg Part No: INA3221AIRGVR; Temperature: -40°C to +125°C
C512 C513 C519 C520 C523 C524 C533 C537-C540 C559-C561 = CAP_NP: Cap, Cer-X5R, 10uF, 10V, 10%, 0603; EN: 102-1-00156; KEY Number: 102-1-00156@2; Mfg: WALSIN TECHNOLOGY CORP.; Mfg Part No: 0603X106K100CT; Temperature: -55°C to +85°C
C531 = CAP_NP: Cap, Cer-NPO, 3.3pF, 25V, +/-0.5pF, 0402; EN: 102-1-02431; KEY Number: 102-1-02431@1; Mfg: WURTH ELECTRONIK, INC; Mfg Part No: 885012005037; Temperature: -55°C to +125°C
C534 = CAP_NP: Cap, Cer-X7R, 1000pF, 50V, 10%, 0402; EN: 102-1-00054; KEY Number: 102-1-00054@3; Mfg: WALSIN TECHNOLOGY CORP.; Mfg Part No: 0402B102K500CT; Temperature: -55°C to +125°C
C535 = CAP_NP: Cap, Cer-JB, 4.7uF, 10V, 10%, 0402; EN: 102-1-01833; KEY Number: 102-1-01833@1; Mfg: TDK CORPORATION; Mfg Part No: C1005JB1A475K050*C; Temperature: -25°C to +85°C
L7 = IND_CORE_B: Ind, Power, 1uH, 30%, 2.45A, 36mE, Shielded, 90MHz, SMD; EN: 103-1-00205; KEY Number: 103-1-00205@1; Mfg: MURATA MANUFACTURING CO,LTD; Mfg Part No: LQH44PN1R0NP0L; Temperature: -40°C to +85°C
R694 = RES: Res, Chip, 523K, 1/16W, 1%, 0402; EN: 101-1-00554; KEY Number: 101-1-00554@2; Mfg: VISHAY; Mfg Part No: CRCW0402523KFK; Temperature: -55°C to +155°C
R695 = RES: Res, Chip, 16.9K, 1/16W, 1%, 0402; EN: 101-1-00411; KEY Number: 101-1-00411@2; Mfg: VISHAY; Mfg Part No: CRCW040216K9FK; Temperature: -55°C to +155°C
R696 = RES: Res, Chip, 120K, 1/16W, 1%, 0402; EN: 101-1-03508; FPLIST: 0402,0402_HD; KEY Number: 101-1-03508@1; Mfg: VISHAY; Mfg Part No: CRCW0402120KFK; Temperature: -55°C to +155°C
R716 R717 = RES: Res, Chip, 10K, 1/16W, 1%, 0402; EN: 101-1-04184; KEY Number: 101-1-04184@1; Mfg: WALSIN TECHNOLOGY CORP.; Mfg Part No: WR04X1002FTL; Temperature: -55°C to +155°C
U46 = IC_TPS62067_WSON-8P_EP: IC, Switcher, 2.9-6Vin, 0.8-6Vout/2A, WSON-8; EN: 301-4-00125; KEY Number: 301-4-00125@1; Mfg: TEXAS INSTRUMENTS
U47 = IC_LDO-FIXED_4P_EP_A_A2: IC, LDO, 1.45-5.5Vin, 2.8Vout/0.5A, X2SON-4; EN: 301-4-01056; KEY Number: 301-4-01056@1; Mfg: TEXAS INSTRUMENTS; Mfg Part No: TLV75528PDQNR; Temperature: -40°C to +125°C
U49 = IC_LDO-FIXED_4P_EP_A_A2: IC, LDO, 1.45-5.5Vin, 2.5Vout/0.5A, X2SON-4; EN: 301-4-01058; KEY Number: 301-4-01058@1; Mfg: TEXAS INSTRUMENTS; Mfg Part No: TLV75525PDQNR; Temperature: -40°C to +125°C
U51 = IC_TPS51200_SON-10P_EP: IC, TPS51200, Sink/Source DDR Termination Regulator, SON-10; EN: 301-0-00219; KEY Number: 301-0-00219@1; Mfg: TEXAS INSTRUMENTS
U55 = IC_BD2204_CSP-6P_A1: IC, BD2204, Power supply switch IC for SD card, VCSP50L1-6; EN: 301-4-00701; KEY Number: 301-4-00701@1; Mfg: ROHM; Mfg Part No: BD2204GUL-**; Temperature: -40°C to +85°C
BH1 = BATT_HOLDER_2P: Battery Holder, 2032, SMD; EN: 401-1-00001; KEY Number: 401-1-00001@2; Mfg: MEMORY PROTECTION DEVICE
C63 C64 C66 C68-C72 C74 C75 C78-C84 C86 C88 C90 C92-C94 C98 C99 C101 C104 C107 C108 C110 C357 C408 = CAP_NP: Cap, Cer-X5R, 0.22uF, 10V, 10%, 0402; EN: 102-1-00210; FPLIST: 0402,0402_CIR_A1; KEY Number: 102-1-00210@1; Mfg: MURATA MANUFACTURING CO,LTD; Mfg Part No: GRM155R61A224KE19D; Temperature: -55°C to +85°C
C67 C76 C77 C87 C89 C91 C95 C97 C100 C109 C111 C115 C116 = CAP_NP: Cap, Cer-X5R, 2.2uF, 6.3V, 20%, 0402; EN: 102-1-01843; KEY Number: 102-1-01843@2; Mfg: WALSIN TECHNOLOGY CORP.; Mfg Part No: 0402X225M6R3C*; Temperature: -55°C to +85°C
C96 C557 = CAP_NP: Cap, Cer-X5R, 4.7uF, 10V, 10%, 0603; EN: 102-1-01650; KEY Number: 102-1-01650@2; Mfg: WALSIN TECHNOLOGY CORP.; Mfg Part No: 0603X475K100CT; Temperature: -55°C to +85°C
D34 = DIODE_SCH: Diode, Schottky, 1A, 30V, 1.67W, POWERDI-123; EN: 106-2-00007; KEY Number: 106-2-00007@1; Mfg: DIODES INCORPORATED; Temperature: -65°C to +150°C
U7 = IC_IMX7D_BGA-541P_CUST_A1: IC, uP, IMX7D, Dual Core ARM cortex-A7 Application Processor, 1GHz, MAPBGA-541; EN: 301-1-00396; KEY Number: 301-1-00396@2; Mfg: NXP SEMICONDUCTORS; SPLIT_INST: TRUE; SWAP_INFO: (S1+S2+S3+S4+S5+S6+S7+S8+S9+S10+S11+S12+S13+S14+S15); Temperature: -20°C to +105°C
Z1 = BATT_CELL_NON_CAD: Battery, Coin-Cell, Li-ion, 3V, 225mAh, 20mm, 2032, Holder Mount; EN: 204-1-00002; KEY Number: 204-1-00002@1; Mfg: PANASONIC; Mfg Part No: CR2032; Temperature: -30°C to +60°C
C102 C103 C105 C106 C366 = CAP_NP: Cap, Cer-NPO, 18pF, 50V, 5%, 0402; EN: 102-1-01806; KEY Number: 102-1-01806@1; Mfg: MURATA MANUFACTURING CO,LTD; Mfg Part No: GRM1555C1H180JA01D; Temperature: -55°C to +125°C
C112-C114 = CAP_NP: Cap, Cer-X5R, 0.47uF, 10V, 10%, 0402; EN: 102-1-00209; KEY Number: 102-1-00209@2; Mfg: WALSIN TECHNOLOGY CORP.; Mfg Part No: 0402X474K100CT; Temperature: -55°C to +85°C
R36 = RES: Res, Chip, 4.75M, 1/16W, 1%, 0402; EN: 101-1-00646; KEY Number: 101-1-00646@2; Mfg: VISHAY; Mfg Part No: CRCW04024M75FK; Temperature: -55°C to +155°C
R38 = RES: Res, Chip, 1M, 1/16W, 1%, 0402; EN: 101-1-00581; KEY Number: 101-1-00581@2; Mfg: VISHAY; Mfg Part No: CRCW04021M00FK; Temperature: -55°C to +155°C
R39 R41-R44 R49 R286-R291 R436-R447 = RES: Res, Chip, 22E, 1/16W, 5%, 0402; EN: 101-1-02729; KEY Number: 101-1-02729@3; Mfg: WALSIN TECHNOLOGY CORP.; Mfg Part No: WR04X220JTL; Temperature: -55°C to +155°C
R109 = RES: Res, Chip, 10E, 1/16W, 1%, AEC-Q200, 0402; EN: 101-1-00101; KEY Number: 101-1-00101@2; Mfg: VISHAY; Mfg Part No: CRCW040210R0FKED; Temperature: -55°C to +155°C
R110 = RES: Res, Chip, 33E, 1/16W, 1%, 0402; EN: 101-1-03680; KEY Number: 101-1-03680@2; Mfg: WALSIN TECHNOLOGY CORP.; Mfg Part No: WR04X33R0FTL; Temperature: -55°C to +155°C
R525-R528 R530 R532 = RES: Res, Chip, 49.9E, 1/16W, 1%, 0402; EN: 101-1-00168; KEY Number: 101-1-00168@3; Mfg: WALSIN TECHNOLOGY CORP.; Mfg Part No: WR04X49R9FTL; Temperature: -55°C to +155°C
U41 = IC_EEPROM-I2C_8P_C: IC, EEPROM, 64KB, 400KHz, I2C, SOIC-8; EN: 301-2-00416; KEY Number: 301-2-00416@1; Mfg: MICROCHIP; Mfg Part No: 24AA512-I/SN; Temperature: -40°C to +85°C
X1 = CRYSTAL: XTAL, 32.768KHz, 12.5pF, +/-20ppm, 70K, 3.2x1.5mm, SMD; EN: 108-1-00009; KEY Number: 108-1-00009@3; Mfg: MICRO CRYSTAL; Mfg Part No: CM7V-T1A-32.768KHZ-12.5PF-20PPM-TA-QC; Temperature: -40°C to +85°C
X2 = CRYSTAL_4P: XTAL, 24MHz, 18pF, +/-20ppm, 50E, 2.5x3.2mm, SMD; EN: 108-1-00021; KEY Number: 108-1-00021@1; Mfg: ABRACON CORPORATION; Mfg Part No: ABM8-24.000MHZ-B2

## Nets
5VIN: C394.1 C395.1 F1.2 Q2.4(SOURCE1) Q2.8(SOURCE2) Q17.2(EMITTER) R4.1 R538.2 R539.2
GND: BH1.2(NEG) C1.2(CATHODE) C2.2 C3.2 C40.2 C41.2 C42.2 C44.2 C45.2 C46.2 C47.2 C48.2 C49.2 C50.2 C51.2 C52.2 C53.2 C63.2 C64.2 C65.2 C66.2 C67.2 C68.2 C69.2 C70.2 C71.2 C72.2 C73.2 C74.2 C75.2 C76.2 C77.2 C78.2 C79.2 C80.2 C81.2 C82.2 C83.2 C84.2 C85.2 C86.2 C87.2 C88.2 C89.2 C90.2 C91.2 C92.2 C93.2 C94.2 C95.2 C96.2 C97.2 C98.2 C99.2 C100.2 C101.2 C102.2 C103.2 C104.2 C105.2 C106.2 C107.2 C108.2 C109.2 C110.2 C111.2 C112.2 C113.2 C114.2 C115.2 C116.2 C357.2 C366.2 C395.2 C408.2 C438.2(CATHODE) C439.2 C512.2 C513.2 C518.2 C519.2 C520.2 C523.2 C524.2 C533.2 C534.2 C535.2 C536.2 C537.2 C538.2 C539.2 C540.2 C542.2 C546.2 C550.2 C551.2 C552.2 C553.2 C556.1 C557.2 C559.2 C560.2 C561.2 C566.2 C567.2 C568.2 C569.2 D1.1(K) D17.2(A) H1.6 J1.2 J1.S1 J1.S2 J2.2 P12.1 Q5.2(SOURCE) Q37.2(SOURCE) Q40.2(EMITTER) R8.1 R35.2 R37.1 R40.1 R614.1 R615.2 R616.1 R641.2 R696.1 R717.1 R735.1 R742.1 R764.1 SW1.2(COM) SW4.1 SW4.2 SW9.1 TP30.1 TP31.1 TP32.1 TP33.1 TP34.1 TP35.1 TP36.1 TP37.1 U5.20(L5) U5.21(FB5) U5.22(FB6) U5.23(L6) U5.24(SYS_BU) U5.25(CC) U5.27(IN_BU) U5.49(GND_EP) U7.A1(VSS_001) U7.A3(VSS_002) U7.A6(VSS_003) U7.A9(VSS_004) U7.A13(VSS_005) U7.A17(VSS_006) U7.A21(VSS_007) U7.A25(VSS_008) U7.AA1(VSS_111) U7.AA2(VSS_112) U7.AA6(VSS_113) U7.AA8(VSS_114) U7.AA15(VSS_115) U7.AA23(VSS_116) U7.AB4(VSS_117) U7.AB5(VSS_118) U7.AB7(VSS_119) U7.AB9(VSS_120) U7.AB12(VSS_121) U7.AC6(VSS_122) U7.AC9(VSS_123) U7.AC12(VSS_124) U7.AC15(VSS_125) U7.AC17(VSS_126) U7.AC19(VSS_127) U7.AC21(VSS_128) U7.AC23(VSS_129) U7.AD2(VSS_130) U7.AD5(VSS_131) U7.AD7(VSS_132) U7.AD9(VSS_133) U7.AD12(VSS_134) U7.AE1(VSS_135) U7.AE5(VSS_136) U7.AE7(VSS_137) U7.AE9(VSS_138) U7.AE12(VSS_139) U7.AE24(VSS_140) U7.AE25(VSS_141) U7.B3(VSS_009) U7.B6(VSS_010) U7.B9(VSS_011) U7.B13(VSS_012) U7.B17(VSS_013) U7.B21(VSS_014) U7.C9(VSS_015) U7.C13(VSS_016) U7.C15(VSS_017) U7.C16(VSS_018) U7.C18(VSS_019) U7.C19(VSS_020) U7.D1(VSS_021) U7.D2(VSS_022) U7.D4(VSS_023) U7.D7(VSS_024) U7.D10(VSS_025) U7.D22(VSS_026) U7.F7(VSS_027) U7.F8(VSS_028) U7.F11(VSS_029) U7.F13(VSS_030) U7.G4(VSS_031) U7.G7(VSS_032) U7.G9(VSS_033) U7.G11(VSS_034) U7.G13(VSS_035) U7.G15(VSS_036) U7.G17(VSS_037) U7.G19(VSS_038) U7.G22(VSS_039) U7.H1(VSS_040) U7.H2(VSS_041) U7.J7(VSS_042) U7.J19(VSS_043) U7.K4(VSS_044) U7.K10(VSS_045) U7.K12(VSS_046) U7.K14(VSS_047) U7.K16(VSS_048) U7.K22(VSS_049) U7.L7(VSS_050) U7.L11(VSS_051) U7.L13(VSS_052) U7.L15(VSS_053) U7.L19(VSS_054) U7.M10(VSS_055) U7.M12(VSS_056) U7.M14(VSS_057) U7.M16(VSS_058) U7.M24(VSS_059) U7.M25(VSS_060) U7.N4(VSS_061) U7.N7(VSS_062) U7.N11(VSS_063) U7.N13(VSS_064) U7.N15(VSS_065) U7.N19(VSS_066) U7.P10(VSS_067) U7.P12(VSS_068) U7.P14(VSS_069) U7.P16(VSS_070) U7.R7(VSS_071) U7.R11(VSS_072) U7.R13(VSS_073) U7.R15(VSS_074) U7.R19(VSS_075) U7.R20(VSS_076) U7.R21(VSS_077) U7.R23(VSS_078) U7.T4(VSS_079) U7.T10(VSS_080) U7.T12(VSS_081) U7.T14(VSS_082) U7.T16(VSS_083) U7.T20(VSS_084) U7.U7(VSS_085) U7.U11(VSS_086) U7.U19(VSS_087) U7.U20(VSS_088) U7.U23(VSS_089) U7.V20(VSS_090) U7.W1(VSS_091) U7.W2(VSS_092) U7.W4(VSS_093) U7.W7(VSS_094) U7.W9(VSS_095) U7.W11(VSS_096) U7.W13(VSS_097) U7.W15(VSS_098) U7.W17(VSS_099) U7.W19(VSS_100) U7.W20(VSS_101) U7.W23(VSS_102) U7.Y6(VSS_103) U7.Y13(VSS_104) U7.Y14(VSS_105) U7.Y15(VSS_106) U7.Y16(VSS_107) U7.Y17(VSS_108) U7.Y18(VSS_109) U7.Y19(VSS_110) U41.1(A0) U41.2(A1) U41.3(A2) U41.4(VSS) U41.7(WP) U46.1(PGND) U46.3(AGND) U46.9(GND_EP) U47.2(GND) U47.5(GND_EP) U49.2(GND) U49.5(GND_EP) U50.3(GND) U50.5(A0) U50.17(GND_EP) U51.4(PGND) U51.8(GND) U51.11(EP) U52.3(GND) U52.17(GND_EP) U55.B2(GND) X2.2(GND1) X2.4(GND2) ; also on sheet 8 9 10 11 13 14 15 16 17 18 19 20 21
PVCC_ENET_CAP: C115.1 U7.H14(PVCC_ENET_CAP)
PVCC_EPDC_LCD_CAP: C116.1 U7.N17(PVCC_EPDC_LCD_CAP)
PVCC_GPIO_CAP: C100.1 U7.V10(PVCC_GPIO_CAP)
PVCC_SAI_SD_CAP: C111.1 U7.J9(PVCC_SAI_SD_CAP)
VDD_1P2_CAP: C88.1 C89.1 U7.H12(VDD_USB_H_1P2) U7.U9(VDD_1P2_CAP)
VDD_1V8: C561.1 FB2.1 R30.2 R32.1 R45.1 R325.1 R722.2 TP77.1 U5.39(FB3) U50.1(IN3-) U55.A2(VIN2) ; also on sheet 8 10 13 15 18 19
VDD_1V8_L3: L5.1 U5.38(L3)
VDD_1V8_SNS: C42.1 C546.1 C552.1 L5.2 R722.1 U5.5(IN_LDO1) U50.2(IN3+)
VDD_1V35: C533.1 C537.1 R716.2 R721.2 TP78.1 U5.41(FB2) U50.14(IN2-) U51.2(VLDOIN) ; also on sheet 9
VDD_1V35_L2: L4.1 U5.42(L2)
VDD_1V35_SNS: C41.1 C551.1 L4.2 R721.1 U50.15(IN2+)
VDD_3V3: C98.1 C99.1 C101.1 C109.1 C112.1 C113.1 C114.1 C408.1 C536.1 C566.1 C567.1 FB38.1 R46.1 R685.1 R686.1 R692.1 R715.1 R727.2 R728.2 R731.2 R732.2 R749.2 R750.2 R751.1 TP80.1 U7.F12(NVCC_SAI) U7.H16(NVCC_ENET1) U7.K18(NVCC_LCD) U7.L17(NVCC_EPDC2) U7.M18(NVCC_EPDC1) U7.P8(NVCC_GPIO1) U7.T8(NVCC_GPIO2) U41.8(VCC) U50.4(VS) U50.16(VPU) U51.10(VIN) U52.1(IN3-) U52.4(VS) U52.16(VPU) ; also on sheet 8 11 12 13 15 16 17 18 19 20 21
VDD_3V3_L4A: L6.1 U5.13(L4A)
VDD_3V3_L4B: L6.2 U5.14(L4B)
VDD_3V3_PERI: C518.1 C520.1 C524.1 C531.1 FB38.2 L7.2 R694.2 TP84.1 U47.4(IN) U49.4(IN) ; also on sheet 10
VDD_3V3_SD: C45.1 C560.1 U5.30(LS1) U55.A1(VIN1)
VDD_3V3_SNS: C46.1 C47.1 R728.1 U5.15(DCDC4) U5.31(IN_LS1) U52.2(IN3+)
VDD_5V: R730.2 TP82.1 U52.11(IN1-) ; also on sheet 11 16 17
VDD_5V_SNS: C48.1 C49.1 R730.1 U5.7(LS3) U5.33(LS2) U52.12(IN1+)
VDD_DCJACK_5VIN: F1.1 J1.1
VDD_DDR_VTT: C538.1 C539.1 C540.1 U51.3(VO) U51.5(VOSNS)
VDD_LDO_1V5: R729.2 TP81.1 U52.14(IN2-) ; also on sheet 10
VDD_LDO_1V5_SNS: C44.1 C553.1 R729.1 U5.4(LDO1) U52.15(IN2+)
VDD_LDO_2V5: C523.1 TP86.1 U49.1(OUT) ; also on sheet 13
VDD_LDO_2V8: C519.1 TP85.1 U47.1(OUT) ; also on sheet 19
VDD_LPSR_1P0_CAP: C97.1 U7.AC5(VDD_LPSR_1P0_CAP)
VDD_LPSR_IN: C96.1 R32.2 U7.W6(VDD_LPSR_IN)
VDD_SD: C104.1 C559.1 U7.E7(NVCC_SD1) U55.B1(VOUT) ; also on sheet 18
VDD_SD2: C108.1 R325.2 U7.H8(NVCC_SD2)
VDD_SD3: C110.1 R45.2 R46.2 U7.K8(NVCC_SD3) ; also on sheet 18
VDD_SNVS_1P8_CAP: C95.1 U7.AE8(VDD_SNVS_1P8_CAP)
VDD_SOC_ARM: C63.1 C64.1 C65.1 C68.1 C69.1 C70.1 C71.1 C72.1 C73.1 C79.1 C80.1 C81.1 C82.1 C83.1 C84.1 C85.1 R718.2 TP79.1 U5.47(FB1) U7.C14(VDD_SOC_IN_01) U7.C17(VDD_ARM_IN_01) U7.C20(VDD_ARM_IN_02) U7.D14(VDD_SOC_IN_02) U7.D17(VDD_ARM_IN_03) U7.D20(VDD_ARM_IN_04) U7.F3(VDD_SOC_IN_03) U7.F4(VDD_SOC_IN_04) U7.F18(VDD_SOC_IN_05) U7.F19(VDD_SOC_IN_06) U7.F22(VDD_ARM_IN_05) U7.F23(VDD_ARM_IN_06) U7.J3(VDD_SOC_IN_07) U7.J4(VDD_SOC_IN_08) U7.J22(VDD_ARM_IN_07) U7.J23(VDD_ARM_IN_08) U7.M3(VDD_SOC_IN_09) U7.M4(VDD_SOC_IN_10) U7.P18(VDD_SOC_IN_11) U7.R3(VDD_SOC_IN_12) U7.R4(VDD_SOC_IN_13) U7.R17(VDD_SOC_IN_14) U7.T18(VDD_SOC_IN_15) U7.U13(VDD_SOC_IN_16) U7.U15(VDD_SOC_IN_17) U7.U17(VDD_SOC_IN_18) U7.V12(VDD_SOC_IN_19) U7.V14(VDD_SOC_IN_20) U7.V16(VDD_SOC_IN_21) U7.V18(VDD_SOC_IN_22) U50.11(IN1-) ; also on sheet 13
VDD_SOC_ARM_L1: L3.1 U5.48(L1)
VDD_SOC_ARM_SNS: C40.1 C550.1 L3.2 R718.1 U50.12(IN1+)
VDDA_1P0_CAP: C86.1 C87.1 U7.V3(VDDA_1P0_CAP)
VDDA_1P8: C90.1 C91.1 C107.1 D34.2(A) FB2.2 U7.V5(VDD_XTAL_1P8) U7.V6(VDDA_1P8_01) U7.W5(VDDA_1P8_02)
VDDA_PHY_1P8: C66.1 C67.1 C78.1 C357.1 U7.J13(VDDA_MIPI_1P8) U7.Y9(VDDA_PHY_1P8) U7.Y10(PCIE_VPH) U7.Y11(PCIE_VPH_TX) U7.Y12(PCIE_VPH_RX)
VDDD_1P0_CAP: C74.1 C75.1 C76.1 C77.1 U7.AA9(VDDD_1P0_CAP) U7.AA10(PCIE_VP) U7.AA11(PCIE_VP_TX) U7.AA12(PCIE_VP_RX) U7.J15(VDD_MIPI_1P0_01) U7.J17(VDD_MIPI_1P0_02)
ALS_INT: U7.J20(EPDC_SDLE) ; also on sheet 17
AUDIO_MCLK: R110.2 ; also on sheet 11
AUDIO_RXD: R485.2 ; also on sheet 11
AUDIO_RXD_R: R485.1 U7.D16(ENET1_TX_CLK)
AUDIO_TXC: R486.2 ; also on sheet 11
AUDIO_TXC_R: R486.1 U7.D15(ENET1_RX_CLK)
AUDIO_TXD: R483.2 ; also on sheet 11
AUDIO_TXD_R: R483.1 U7.D19(ENET1_COL)
AUDIO_TXFS: R487.2 ; also on sheet 11
AUDIO_TXFS_R: R487.1 U7.E19(ENET1_CRS)
BASE_PNP: Q35.2(BASE1) Q35.5(BASE2) Q35.6(COLLECTOR2) R615.1
BAT_CTRL: Q32.3(GATE) R613.1 R614.2
BAT_IN: C569.1 J2.1 Q32.4(SOURCE1) Q32.8(SOURCE2)
BOOT_MODE0: U7.P4(BOOT_MODE0) ; also on sheet 21
BOOT_MODE1: U7.P5(BOOT_MODE1) ; also on sheet 21
BUCK_FB: C531.2 R695.1 R696.2 U46.4(FB)
BUCK_FB_L: L7.1 U46.2(SW)
BUCK_PG: R692.2 U7.L25(EPDC_D09) U46.6(PG)
CAN_STB: R381.1 ; also on sheet 17
CC_RES: BH1.1(POS) C557.1 R737.1
CCM_CLK1_N: TP8.1 U7.Y1(CCM_CLK1_N)
CCM_CLK1_P: TP7.1 U7.Y2(CCM_CLK1_P)
CCM_CLK2: R641.1 TP9.1 U7.W3(CCM_CLK2)
Codec_GPIO_INT: U7.K24(EPDC_BDR0) ; also on sheet 11
COLL_GPIO3: Q41.3(COLLECTOR) R752.2 R763.1
COLL_PMIC_LED: D33.1(K) Q40.3(COLLECTOR)
COLLECTOR_PNP: Q34.3(GATE) Q35.3(COLLECTOR1) R616.2
CSENS1_I2C_SCL: U50.6(SCL) ; also on sheet 12
CSENS1_I2C_SDA: U50.7(SDA) ; also on sheet 12
CSENS1_PV: R727.1 U7.L23(EPDC_D11) U50.10(PV)
CSENS2_A0: R732.1 U52.5(A0)
CSENS2_I2C_SCL: U52.6(SCL) ; also on sheet 12
CSENS2_I2C_SDA: U52.7(SDA) ; also on sheet 12
CSENS2_PV: R731.1 U7.L24(EPDC_D10) U52.10(PV)
CSI_PWDN: U7.G25(EPDC_SDCE0) ; also on sheet 19
DC34_SEL: R37.2 U5.17(DC34_SEL)
DC_SW: R12.1 SW1.1
DC_SW_CTL: C394.2 D20.1(K) Q2.3(GATE) R12.2 R539.1
DDR_VREF: C535.1 U51.6(REFOUT) ; also on sheet 9
EEPROM_I2C1_SCL: U41.6(SCL) ; also on sheet 12
EEPROM_I2C1_SDA: U41.5(SDA) ; also on sheet 12
EMI_GPIO3: Q41.2(EMITTER) R764.2
ESPI3_MISO: U7.D9(SAI2_TXFS) ; also on sheet 17
ESPI3_MOSI: U7.D8(SAI2_TXC) ; also on sheet 17
ESPI3_SCLK: U7.E9(SAI2_RXD) ; also on sheet 17
FUSE_FSOURCE: C93.1 R30.1 U7.V8(FUSE_FSOURCE)
GPANAIO: TP6.1 U7.V4(GPANAIO)
GPIO1: R762.1 U5.11(GPIO1)
GPIO3: R752.1 U5.26(GPIO3)
GPIO_EPDC_D4: C366.1 TP10.1 U7.N22(EPDC_D04)
GPIO_SD3_CLK: R444.2 U7.C1(SD3_CLK)
GPIO_SD3_CMD: R445.2 U7.E1(SD3_CMD)
GPIO_SD3_DATA0: R436.2 U7.B2(SD3_DATA0)
GPIO_SD3_DATA1: R437.2 U7.A2(SD3_DATA1)
GPIO_SD3_DATA2: R439.2 U7.G2(SD3_DATA2)
GPIO_SD3_DATA3: R438.2 U7.F1(SD3_DATA3)
GPIO_SD3_DATA4: R440.2 U7.F2(SD3_DATA4)
GPIO_SD3_DATA5: R441.2 U7.E2(SD3_DATA5)
GPIO_SD3_DATA6: R443.2 U7.C2(SD3_DATA6)
GPIO_SD3_DATA7: R442.2 U7.B1(SD3_DATA7)
GPIO_SD3_RESET_B: R446.2 U7.G1(~{SD3_RESET})
GPIO_SD3_STROBE: R447.2 U7.J1(SD3_STROBE)
I2C4_SCL: U7.C12(SAI1_RXFS) ; also on sheet 12
I2C4_SDA: U7.D12(SAI1_RXC) ; also on sheet 12
INT_LDO: C542.1 U5.35(INT_LDO)
JTAG_MOD: U7.U1(JTAG_MOD) ; also on sheet 20
JTAG_TCK: U7.U5(JTAG_TCK) ; also on sheet 20
JTAG_TDI: U7.U3(JTAG_TDI) ; also on sheet 20
JTAG_TDO: U7.U6(JTAG_TDO) ; also on sheet 20
JTAG_TMS: U7.U4(JTAG_TMS) ; also on sheet 20
JTAG_TRST_B: U7.U2(~{JTAG_TRST}) ; also on sheet 20
LCD1_CLK: R109.1 ; also on sheet 17
LCD1_DATA0: U7.D21(LCD1_DATA00) ; also on sheet 17
LCD1_DATA1: U7.A22(LCD1_DATA01) ; also on sheet 17
LCD1_DATA2: U7.B22(LCD1_DATA02) ; also on sheet 17
LCD1_DATA3: U7.A23(LCD1_DATA03) ; also on sheet 17
LCD1_DATA4: U7.C22(LCD1_DATA04) ; also on sheet 17 21
LCD1_DATA5: U7.B23(LCD1_DATA05) ; also on sheet 17 21
LCD1_DATA6: U7.A24(LCD1_DATA06) ; also on sheet 17 21
LCD1_DATA7: U7.F20(LCD1_DATA07) ; also on sheet 17
LCD1_DATA8: U7.E21(LCD1_DATA08) ; also on sheet 17
LCD1_DATA9: U7.C23(LCD1_DATA09) ; also on sheet 17
LCD1_DATA10: U7.B24(LCD1_DATA10) ; also on sheet 17 21
LCD1_DATA11: U7.G20(LCD1_DATA11) ; also on sheet 17 21
LCD1_DATA12: U7.F21(LCD1_DATA12) ; also on sheet 17 21
LCD1_DATA13: U7.E22(LCD1_DATA13) ; also on sheet 17 21
LCD1_DATA14: U7.D23(LCD1_DATA14) ; also on sheet 17 21
LCD1_DATA15: U7.C24(LCD1_DATA15) ; also on sheet 17
LCD1_DATA16: U7.B25(LCD1_DATA16) ; also on sheet 17
LCD1_DATA17: U7.G21(LCD1_DATA17) ; also on sheet 17
LCD1_DATA18: U7.E23(LCD1_DATA18) ; also on sheet 17
LCD1_DATA19: U7.D24(LCD1_DATA19) ; also on sheet 17
LCD1_DATA20: U7.C25(LCD1_DATA20) ; also on sheet 17
LCD1_DATA21: U7.E24(LCD1_DATA21) ; also on sheet 17
LCD1_DATA22: U7.D25(LCD1_DATA22) ; also on sheet 17
LCD1_DATA23: U7.G23(LCD1_DATA23) ; also on sheet 17
LCD1_ENABLE: U7.F25(LCD1_ENABLE) ; also on sheet 17
LCD1_HSYNC: U7.E25(LCD1_HSYNC) ; also on sheet 17
LCD1_RESET: U7.C21(LCD1_RESET) ; also on sheet 17
LCD1_VSYNC: U7.F24(LCD1_VSYNC) ; also on sheet 17
LCD_PWR_EN: U7.G24(EPDC_SDCE1) ; also on sheet 17
LED_BOOT_COMPL: U7.H23(EPDC_SDCE2) ; also on sheet 16
LED_BOOT_PROC: U7.H22(EPDC_SDCE3) ; also on sheet 16
MIPI_VREG_0P4V: C92.1 U7.H18(MIPI_VREG_0P4V)
MX7_ONOFF: U7.AC8(ONOFF) ; also on sheet 16
OVRPRTC: Q5.1(GATE) R6.1 R8.2
OVRPRTC_LED: D2.1(K) Q5.3(DRAIN)
OVRPRTC_LED_PWR: D2.2(A) R4.2
PMIC_AC_DET: C556.2 Q37.3(DRAIN) R448.1 SW9.2 U5.9(AC_DET)
PMIC_ENABLE: R687.1 R735.2 U5.46(PWR_EN) U7.AB8(SNVS_PMIC_ON_REQ) ; also on sheet 19
PMIC_ENABLE_ACDET: Q37.1(GATE) ; also on sheet 19
PMIC_GPIO1: R749.1 R762.2 U46.5(EN) U47.3(EN) U49.3(EN) U51.7(EN) U55.A3(EN)
PMIC_I2C1_SCL: U5.3(SCL) ; also on sheet 12
PMIC_I2C1_SDA: U5.2(SDA) ; also on sheet 12
PMIC_INT_B: R47.2 R685.2 ; also on sheet 8
PMIC_PB_B: R689.1 SW4.3 SW4.4 U5.44(PB#)
PMIC_PFI: R31.1 R40.2 U5.16(PFI)
PMIC_PFO_B: R686.2 U5.10(PFO#) ; also on sheet 8
PMIC_PWR: C50.1 C51.1 C52.1 C53.1 C438.1(ANODE) C439.1 C512.1 C513.1 C568.1 Q32.1(DRAIN1) Q32.2(DRAIN2) Q32.5(DRAIN3) Q32.6(DRAIN4) Q32.7(DRAIN5) Q34.1(DRAIN1) Q34.2(DRAIN2) Q34.5(DRAIN3) Q34.6(DRAIN4) Q34.7(DRAIN5) Q35.4(EMITTER2) R31.2 R448.2 R689.2 R738.2 U5.1(IN_DCDC1) U5.6(IN_LS3) U5.12(IN_DCDC4) U5.32(IN_LS2) U5.36(IN_BIAS) U5.37(IN_DCDC3) U5.43(IN_DCDC2) U46.7(AVIN) U46.8(PIN)
PMIC_SD_VSEL: R742.2 U55.B3(SEL) ; also on sheet 8
PMIC_STBY: Q41.1(BASE) R753.1
PMIC_STBY_R: R753.2 U7.AC7(PMIC_STBY_REQ)
PMIC_WAKE_B: R751.2 U5.40(WAKEUP#) U7.J25(EPDC_GDCLK)
POR_B: Q40.1(BASE) R690.2 R750.1 U7.R6(~{POR}) ; also on sheet 20
PSU_5V0: C1.1(ANODE) C2.1 C3.1 P12.2 Q2.1(DRAIN1) Q2.2(DRAIN2) Q2.5(DRAIN3) Q2.6(DRAIN4) Q2.7(DRAIN5) Q34.4(SOURCE1) Q34.8(SOURCE2) Q35.1(EMITTER1) R1.1 R613.2 TP1.1
PWR_LED: D1.2(A) R1.2
PWR_OV_BASE: Q17.1(BASE) R537.1
PWR_OV_CTL: D17.1(K) R537.2 R538.1
PWR_OVP_LED: D20.2(A) Q17.3(COLLECTOR) R6.2
QSPIA_DA0: TP11.1 U7.P20(EPDC_D00) ; also on sheet 18
QSPIA_DA1: U7.P21(EPDC_D01) ; also on sheet 18
QSPIA_DA2: U7.N20(EPDC_D02) ; also on sheet 18
QSPIA_DA3: U7.N21(EPDC_D03) ; also on sheet 18
QSPIA_SCLK: U7.M20(EPDC_D05) ; also on sheet 18
QSPIA_SS0_B: U7.M21(EPDC_D06) ; also on sheet 18
RES_BUCK_FB: R694.1 R695.2
RES_CAN_STB: R381.2 U7.L20(EPDC_D14)
RES_INT_B: R47.1 U5.45(INT#)
RES_PMIC_LED: D33.2(A) R738.1
RES_POR_B: R690.1 U5.8(PGOOD)
RES_TP_BUSY: R380.1 U7.K25(EPDC_D15)
RGMII1_RX_CTL: U7.E15(ENET1_RX_CTL) ; also on sheet 13
RGMII1_RXC: U7.F15(ENET1_RXC) ; also on sheet 13
RGMII1_RXD0: U7.E14(ENET1_RD0) ; also on sheet 13
RGMII1_RXD1: U7.F14(ENET1_RD1) ; also on sheet 13
RGMII1_RXD2: U7.D13(ENET1_RD2) ; also on sheet 13
RGMII1_RXD3: U7.E13(ENET1_RD3) ; also on sheet 13
RGMII1_TX_CTL: R532.1 ; also on sheet 13
RGMII1_TXC: R527.1 ; also on sheet 13
RGMII1_TXD0: R528.1 ; also on sheet 13
RGMII1_TXD1: R526.1 ; also on sheet 13
RGMII1_TXD2: R525.1 ; also on sheet 13
RGMII1_TXD3: R530.1 ; also on sheet 13
RGMII_TCTRL: R532.2 U7.E16(ENET1_TX_CTL)
RGMII_TD0: R528.2 U7.F17(ENET1_TD0)
RGMII_TD1: R526.2 U7.E17(ENET1_TD1)
RGMII_TD2: R525.2 U7.E18(ENET1_TD2)
RGMII_TD3: R530.2 U7.D18(ENET1_TD3)
RGMII_TXC: R527.2 U7.F16(ENET1_TXC)
RTC_XO: C103.1 R285.2 X1.2
RTC_XTALI: C102.1 R36.1 U7.AE6(RTC_XTALI) X1.1
RTC_XTALO: R36.2 R285.1 U7.AD6(RTC_XTALO)
SAI1_MCLK: R110.1 U7.E10(SAI1_MCLK)
SD1_CD_B: U7.C6(~{SD1_CD}) ; also on sheet 18
SD1_CLK: R49.1 ; also on sheet 18
SD1_CMD: R39.1 ; also on sheet 18
SD1_DATA0: R41.1 ; also on sheet 18
SD1_DATA1: R42.1 ; also on sheet 18
SD1_DATA2: R43.1 ; also on sheet 18
SD1_DATA3: R44.1 ; also on sheet 18
SD1_RESET_B: U7.B4(~{SD1_RESET}) ; also on sheet 18
SD1_WP: U7.C4(SD1_WP) ; also on sheet 18
SD2_CLK: R286.1 ; also on sheet 15
SD2_CMD: R287.1 ; also on sheet 15
SD2_DATA0: R288.1 ; also on sheet 15
SD2_DATA1: R289.1 ; also on sheet 15
SD2_DATA2: R290.1 ; also on sheet 15
SD2_DATA3: R291.1 ; also on sheet 15
SD3_CLK: R444.1 ; also on sheet 18
SD3_CMD: R445.1 ; also on sheet 18
SD3_DATA0: R436.1 ; also on sheet 18
SD3_DATA1: R437.1 ; also on sheet 18
SD3_DATA2: R439.1 ; also on sheet 18
SD3_DATA3: R438.1 ; also on sheet 18
SD3_DATA4: R440.1 ; also on sheet 18
SD3_DATA5: R441.1 ; also on sheet 18
SD3_DATA6: R443.1 ; also on sheet 18
SD3_DATA7: R442.1 ; also on sheet 18
SD3_RESET_B: R446.1 ; also on sheet 18
SD3_STROBE: R447.1 ; also on sheet 18
SOC_SD1_CLK: R49.2 U7.B5(SD1_CLK)
SOC_SD1_CMD: R39.2 U7.C5(SD1_CMD)
SOC_SD1_DATA0: R41.2 U7.A5(SD1_DATA0)
SOC_SD1_DATA1: R42.2 U7.D6(SD1_DATA1)
SOC_SD1_DATA2: R43.2 U7.A4(SD1_DATA2)
SOC_SD1_DATA3: R44.2 U7.D5(SD1_DATA3)
SOC_SD2_CLK: R286.2 U7.E3(SD2_CLK)
SOC_SD2_CMD: R287.2 U7.F6(SD2_CMD)
SOC_SD2_DATA0: R288.2 U7.E4(SD2_DATA0)
SOC_SD2_DATA1: R289.2 U7.E5(SD2_DATA1)
SOC_SD2_DATA2: R290.2 U7.F5(SD2_DATA2)
SOC_SD2_DATA3: R291.2 U7.E6(SD2_DATA3)
ST_LCD_CLK: R109.2 U7.E20(LCD1_CLK)
TEST_MODE: R35.1 U7.P6(TEST_MODE)
TP_BUSY: R380.2 ; also on sheet 17
TP_ESPI3_SS2_B: U7.D3(~{SD2_CD}) ; also on sheet 17
TP_INT_B: U7.K23(EPDC_BDR1) ; also on sheet 17
TPS51200_PG: R715.2 TP76.1 U51.9(PGOOD)
TPS51200_REFIN: C534.1 R716.1 R717.2 U51.1(REFIN)
UART5_CTS: U7.D11(SAI1_TXFS) ; also on sheet 21
UART5_RTS: U7.E11(SAI1_TXD) ; also on sheet 21
USB2ANY_I2C1_SCL: H1.1 ; also on sheet 12
USB2ANY_I2C1_SDA: H1.2 ; also on sheet 12
USR_BT0: U7.G3(~{SD2_RESET}) ; also on sheet 16
USR_BT1: U7.C3(SD2_WP) ; also on sheet 16
VSNVS: C94.1 D34.1(K) R687.2 R737.2 R763.2 U7.AD8(VDD_SNVS_IN) ; also on sheet 16 19
XTALI: C105.1 R38.2 U7.V1(XTALI) X2.1
XTALO: R38.1 R284.1 U7.V2(XTALO)
XTC_XO: C106.1 R284.2 X2.3

Not connected (* = marked no-connect by the designer): H1 3* 4* 5* 7* 8* 9* 10*; SW1 3* S1* S2*; U5 18(IN_CC#)* 19(PGOOD_BU)* 28(N/C_1)* 29(N/C_2)* 34(GPO2)*; U7 AA3(SNVS_TAMPER8)* AA4(SNVS_TAMPER6)* AA5(SNVS_TAMPER4)* AA7(SNVS_TAMPER0)* AB6(SNVS_TAMPER2)* C11(SAI1_TXC)* E8(SAI2_TXD)* E12(SAI1_RXD)* H20(EPDC_SDSHR)* H21(EPDC_SDOE)* H24(EPDC_PWRCOM)* H25(EPDC_GDSP)* J21(EPDC_SDCLK)* J24(EPDC_GDOE)* K20(EPDC_PWRSTAT)* K21(EPDC_GDRL)* L21(EPDC_D13)* L22(EPDC_D12)* M22(EPDC_D07)* M23(EPDC_D08)* Y3(SNVS_TAMPER9)* Y4(SNVS_TAMPER7)* Y5(SNVS_TAMPER5)* Y7(SNVS_TAMPER3)* Y8(SNVS_TAMPER1)*; U50 8(WARNING)* 9(CRITICAL)* 13(TC)*; U52 8(WARNING)* 9(CRITICAL)* 13(TC)*

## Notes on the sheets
sheet 1
- PERIPHERAL 3V3
- DDR3L VREF
- VDD_DDR_VTT Currently not using
- C531 will be replaced by 3.6pF in BOM
- Place the whole section near DDR3L.
  Place C536 near pin 10, C533, C537 near pin 2
- 2V8 LDO
- 2V5 LDO
- SD CARD VOLTAGE SELECT
sheet 2
- Schematics Drafted in : Allegro Design entry CIS 17.2
- REV
- Revision Notes
- Designer
- Approver
- Date
- A1
- First Release
- VVDN
- TI
- 17-06-2019
- 1. R538 Replaced with 300E Resistor
  2. C535 Replaced with 4.7uF, 10V Capacitor
  3. U37 replaced with TPS3808G25DBVR
  4. D34 Made NO MOUNT
  5. R660 Made NO MOUNT, R684 Mounted with 0E
- A2
- VVDN
- TI
- 05-09-2019
- 1. VDD_3V3 Connected to Q6.2. which connects to
  VDD of J28. This is for keeping  SD card VDD
  voltage at 3V3.
  2. Moved the position of I2C1 signals of Header H1
  from pin 9 &10 to pin 1 & 2.
  3. Added Capacitor C578, C579  across SW5 and
  SW6.
  4. PGOOD LED of PMIC connected from PGOOD pin
  of TPS65218D0.
  5. PMIC_STBY from uP used for resetting
  DCDC1 of TPS65218D0.
  6. PMIC_GPIO1 used for enabling DCDC converters
  other than TPS65218D0.
- B1
- VVDN
- TI
- 24-10-2019
- TIXU_MX7D
- Content
- Page No
- Sheet Name
- 01
- COVER PAGE
- 02
- BLOCK DIAGRAM
- 03
- MAIN POWER
- 04
- PMIC
- 05
- POWER DC-DC
- 06
- CPU POWER
- 07
- CPU SIGNAL 1
- 08
- CPU SIGNAL 2
- 09
- DDR3L
- 10
- eMMC/FLASH/SD
- 11
- mini PCIe
- 12
- WiFi BT
- 13
- DEBUG UART/JTAG
- 14
- AUDIO
- 15
- BOOT/UART HEADER
- 16
- CAN/LCD/ALS
- 17
- I2C
- 18
- USB/BUTTON
- 19
- ETHERNET
- 20
- CSI/WATCHDOG/IO
- 21
- MISCELLANEOUS
sheet 3
- BLOCK DIAGRAM
- POWER ARCHITECTURE
sheet 4
- 5V DC POWER
- OVER VOLTAGE PROTECTION
- BATTERY IN
- Note: Over-voltage protection is designed to withstand up to +7V
- ORING
- OVER VOLTAGE INDICATOR
sheet 5
- PMIC
- Output Capacitor for all the power rails -
  Place near the output Inductor
- Input Capacitor for power rails -
  Place near U5 pins 1, 43, 37,12
- Power failure is notified to system
  if PMIC_PWR go below 3.52V
- Place C546 near Pin 5
- Mount if WiFi+BT need more current
- PMIC PB
- GND TEST POINT
- Place C568 near Pin 36
- PMIC AC-DET
- USB2ANY
- GPIO3 is used as the warm reset
  for the PMIC. For this to work set
  DC12_RST bit of PMIC to 1
- In PMIC sequencing replace
  GPIO3 with GPIO1
- PGOOD LED
- CURRENT AND VOLTAGE MONITORING
- I2C ADDR=0x40
- I2C ADDR=0x41
sheet 6
- CPU POWER
- D34 Is recommended in  I.MX7Dual Hardware
  user guide
- COIN CELL
- Place COIN CELL near AD8 of U7
sheet 7
- CPU SIGNAL 1
- I2C4 :
  Audio Codec
  CSI
  PCIe Clock Generator
- SPI
- SNVS left NC/floating
  when no used.
  Also configure with software
- Close to CPU
- SD3.0
- Close to CPU
- WIFI/BT
- eMMC5.0
- Layout Note:R109 should be placed near MX7D
- Layout Note: Series resistors in SD3 must
  close to the CPU for source impedance matching.
- Board ID
- NM
- LCD
  BOOT_CFG
- QSPIA_DQS
- QSPIA_DATA0
- Layout: Place 49E9 Resistors in
   TD[0:3], TXC, TCTRL as close
  to Processor
- QSPI
- RGMII
- SAI-1
  Codec
